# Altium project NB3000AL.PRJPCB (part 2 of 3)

## Sheet FPGA_Bypass_3V3.SCHDOC: FPGA Bypass 3V3
size A4; Organization: Altium Limited.; Address1: Level 3, 12a Rodborough Rd; Address2: Frenchs Forest 2086; Address3: NSW; Address4: AUSTRALIA; DocumentNumber: 58; SheetNumber: 59; SheetTotal: 78; PageSetup: Record=PageOptions|CenterHorizontal=True|CenterVertical=True|PrintScale=0.97|XCorrection=1.00|YCorrection=1.00|PrintKind=0|BorderSize=5000000|LeftOffset=0|BottomOffset=0|Orientation=2|PaperLength=1000|PaperWidth=1000|Scale=100|PaperSource=7|PrintQuality=-4|MediaType=1|DitherType=10|PaperKind=A4 (210 x 297 mm)|PrintScaleMode=1
Used 2 times, as channels USER_DECOUPLING_CAPS_3V3, HOST_DECOUPLING_CAPS_3V3. Parts and nets are listed once, with the designators drawn on the sheet.
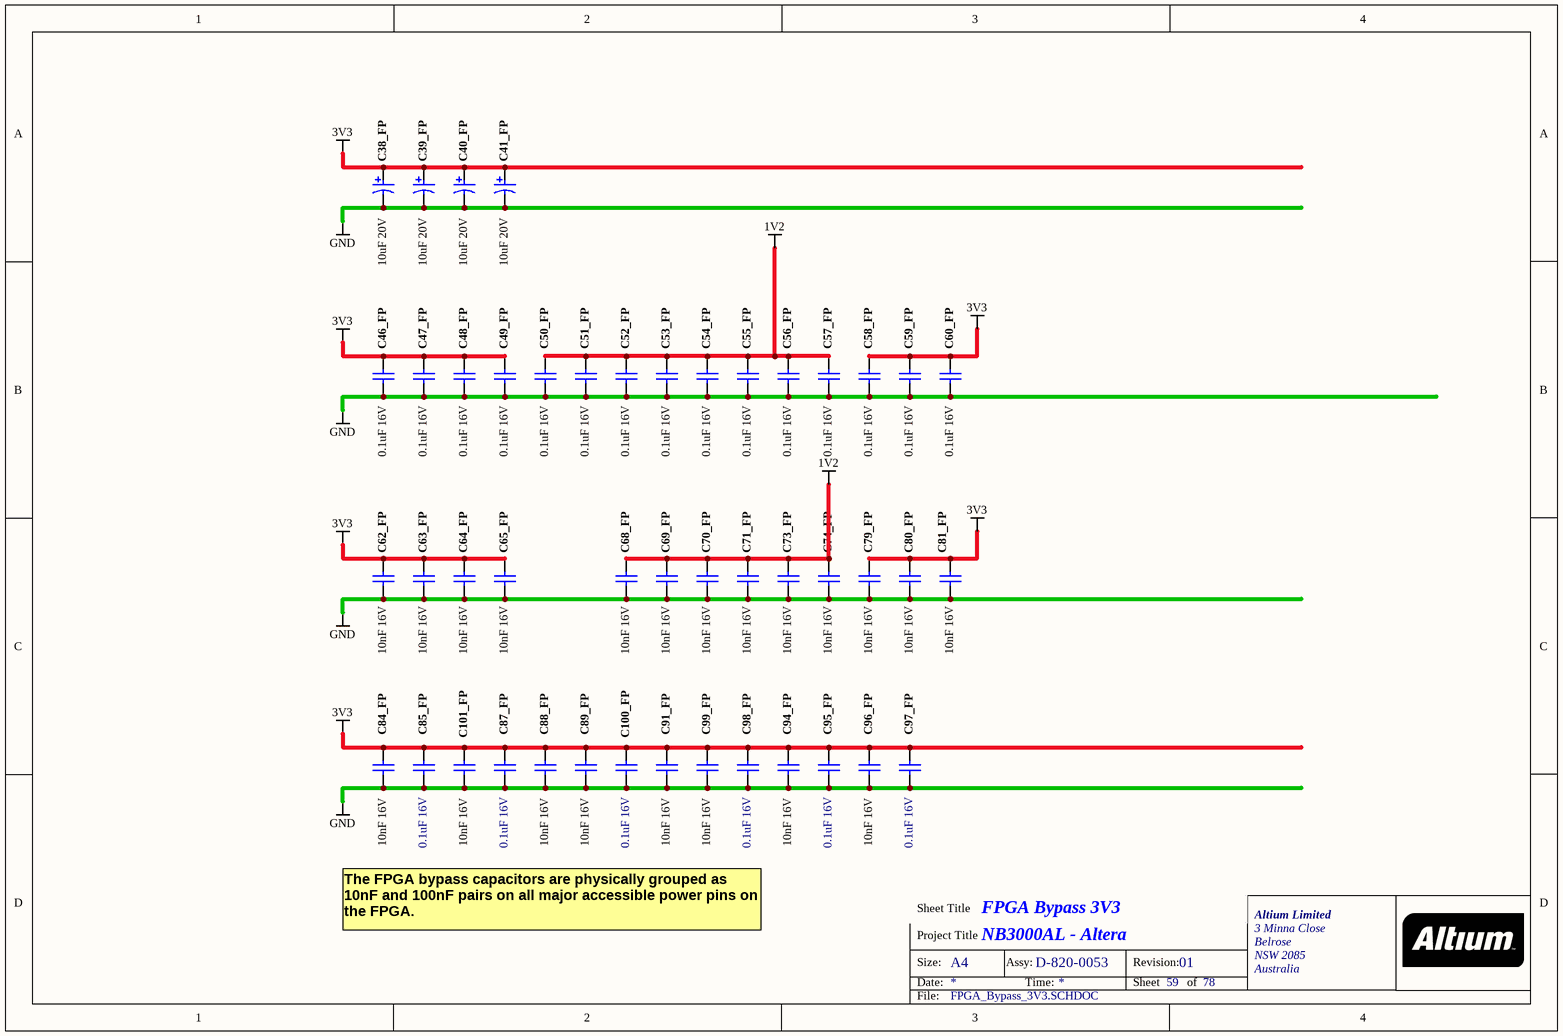
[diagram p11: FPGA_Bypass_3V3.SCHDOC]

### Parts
C38_FP  10uF 20V  [CAPC3528-STAR]
C39_FP  10uF 20V  [CAPC3528-STAR]
C40_FP  10uF 20V  [CAPC3528-STAR]
C41_FP  10uF 20V  [CAPC3528-STAR]
C46_FP  0.1uF 16V  [CAPC1005-STAR]
C47_FP  0.1uF 16V  [CAPC1005-STAR]
C48_FP  0.1uF 16V  [CAPC1005-STAR]
C49_FP  0.1uF 16V  [CAPC1005-STAR]
C50_FP  0.1uF 16V  [CAPC1005-STAR]
C51_FP  0.1uF 16V  [CAPC1005-STAR]
C52_FP  0.1uF 16V  [CAPC1005-STAR]
C53_FP  0.1uF 16V  [CAPC1005-STAR]
C54_FP  0.1uF 16V  [CAPC1005-STAR]
C55_FP  0.1uF 16V  [CAPC1005-STAR]
C56_FP  0.1uF 16V  [CAPC1005-STAR]
C57_FP  0.1uF 16V  [CAPC1005-STAR]
C58_FP  0.1uF 16V  [CAPC1005-STAR]
C59_FP  0.1uF 16V  [CAPC1005-STAR]
C60_FP  0.1uF 16V  [CAPC1005-STAR]
C62_FP  10nF 16V  [CAPC1005-STAR]
C63_FP  10nF 16V  [CAPC1005-STAR]
C64_FP  10nF 16V  [CAPC1005-STAR]
C65_FP  10nF 16V  [CAPC1005-STAR]
C68_FP  10nF 16V  [CAPC1005-STAR]
C69_FP  10nF 16V  [CAPC1005-STAR]
C70_FP  10nF 16V  [CAPC1005-STAR]
C71_FP  10nF 16V  [CAPC1005-STAR]
C73_FP  10nF 16V  [CAPC1005-STAR]
C74_FP  10nF 16V  [CAPC1005-STAR]
C79_FP  10nF 16V  [CAPC1005-STAR]
C80_FP  10nF 16V  [CAPC1005-STAR]
C81_FP  10nF 16V  [CAPC1005-STAR]
C84_FP  10nF 16V  [CAPC1005-STAR]
C85_FP  0.1uF 16V  [CAPC1005-STAR]
C87_FP  0.1uF 16V  [CAPC1005-STAR]
C88_FP  10nF 16V  [CAPC1005-STAR]
C89_FP  10nF 16V  [CAPC1005-STAR]
C91_FP  10nF 16V  [CAPC1005-STAR]
C94_FP  10nF 16V  [CAPC1005-STAR]
C95_FP  0.1uF 16V  [CAPC1005-STAR]
C96_FP  10nF 16V  [CAPC1005-STAR]
C97_FP  0.1uF 16V  [CAPC1005-STAR]
C98_FP  0.1uF 16V  [CAPC1005-STAR]
C99_FP  10nF 16V  [CAPC1005-STAR]
C100_FP  0.1uF 16V  [CAPC1005-STAR]
C101_FP  10nF 16V  [CAPC1005-STAR]

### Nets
1V2: C50_FP.1 C51_FP.1 C52_FP.1 C53_FP.1 C54_FP.1 C55_FP.1 C56_FP.1 C57_FP.1 C68_FP.1 C69_FP.1 C70_FP.1 C71_FP.1 C73_FP.1 C74_FP.1
3V3: C38_FP.1 C39_FP.1 C40_FP.1 C41_FP.1 C46_FP.1 C47_FP.1 C48_FP.1 C49_FP.1 C58_FP.1 C59_FP.1 C60_FP.1 C62_FP.1 C63_FP.1 C64_FP.1 C65_FP.1 C79_FP.1 C80_FP.1 C81_FP.1 C84_FP.1 C85_FP.1 C87_FP.1 C88_FP.1 C89_FP.1 C91_FP.1 C94_FP.1 C95_FP.1 C96_FP.1 C97_FP.1 C98_FP.1 C99_FP.1 C100_FP.1 C101_FP.1
GND: C38_FP.2 C39_FP.2 C40_FP.2 C41_FP.2 C46_FP.2 C47_FP.2 C48_FP.2 C49_FP.2 C50_FP.2 C51_FP.2 C52_FP.2 C53_FP.2 C54_FP.2 C55_FP.2 C56_FP.2 C57_FP.2 C58_FP.2 C59_FP.2 C60_FP.2 C62_FP.2 C63_FP.2 C64_FP.2 C65_FP.2 C68_FP.2 C69_FP.2 C70_FP.2 C71_FP.2 C73_FP.2 C74_FP.2 C79_FP.2 C80_FP.2 C81_FP.2 C84_FP.2 C85_FP.2 C87_FP.2 C88_FP.2 C89_FP.2 C91_FP.2 C94_FP.2 C95_FP.2 C96_FP.2 C97_FP.2 C98_FP.2 C99_FP.2 C100_FP.2 C101_FP.2

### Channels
USER_DECOUPLING_CAPS_3V3: designators end in A
HOST_DECOUPLING_CAPS_3V3: designators end in B

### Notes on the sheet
- The FPGA bypass capacitors are physically grouped as 10nF and 100nF pairs on all major accessible power pins on the FPGA.

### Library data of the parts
C38_FP C39_FP C40_FP C41_FP = D-101-0007: Capacitor, Tantalum, 10uF 10% 20V MCCT-B (3528); Polarity: Polarized
C46_FP C47_FP C48_FP C49_FP C50_FP C51_FP C52_FP C53_FP C54_FP C55_FP C56_FP C57_FP C58_FP C59_FP C60_FP C85_FP C87_FP C95_FP C97_FP C98_FP C100_FP = D-101-0080: Capacitor, Ceramic, 0.1uF 10% 16V 0402 (1005) X7R; Polarity: Non-Polarized
C62_FP C63_FP C64_FP C65_FP C68_FP C69_FP C70_FP C71_FP C73_FP C74_FP C79_FP C80_FP C81_FP C84_FP C88_FP C89_FP C91_FP C94_FP C96_FP C99_FP C101_FP = D-101-0077: Capacitor, Ceramic, 10nF 10% 16V 0402 (1005) X7R; Polarity: Non-Polarized

## Sheet FPGA_NonIO.SchDoc: User FPGA Pwr and Programming
size A3; Organization: Altium Limited.; Address1: Level 3, 12a Rodborough Rd; Address2: Frenchs Forest 2086; Address3: NSW; Address4: AUSTRALIA; DocumentNumber: 8; SheetNumber: 9; SheetTotal: 78
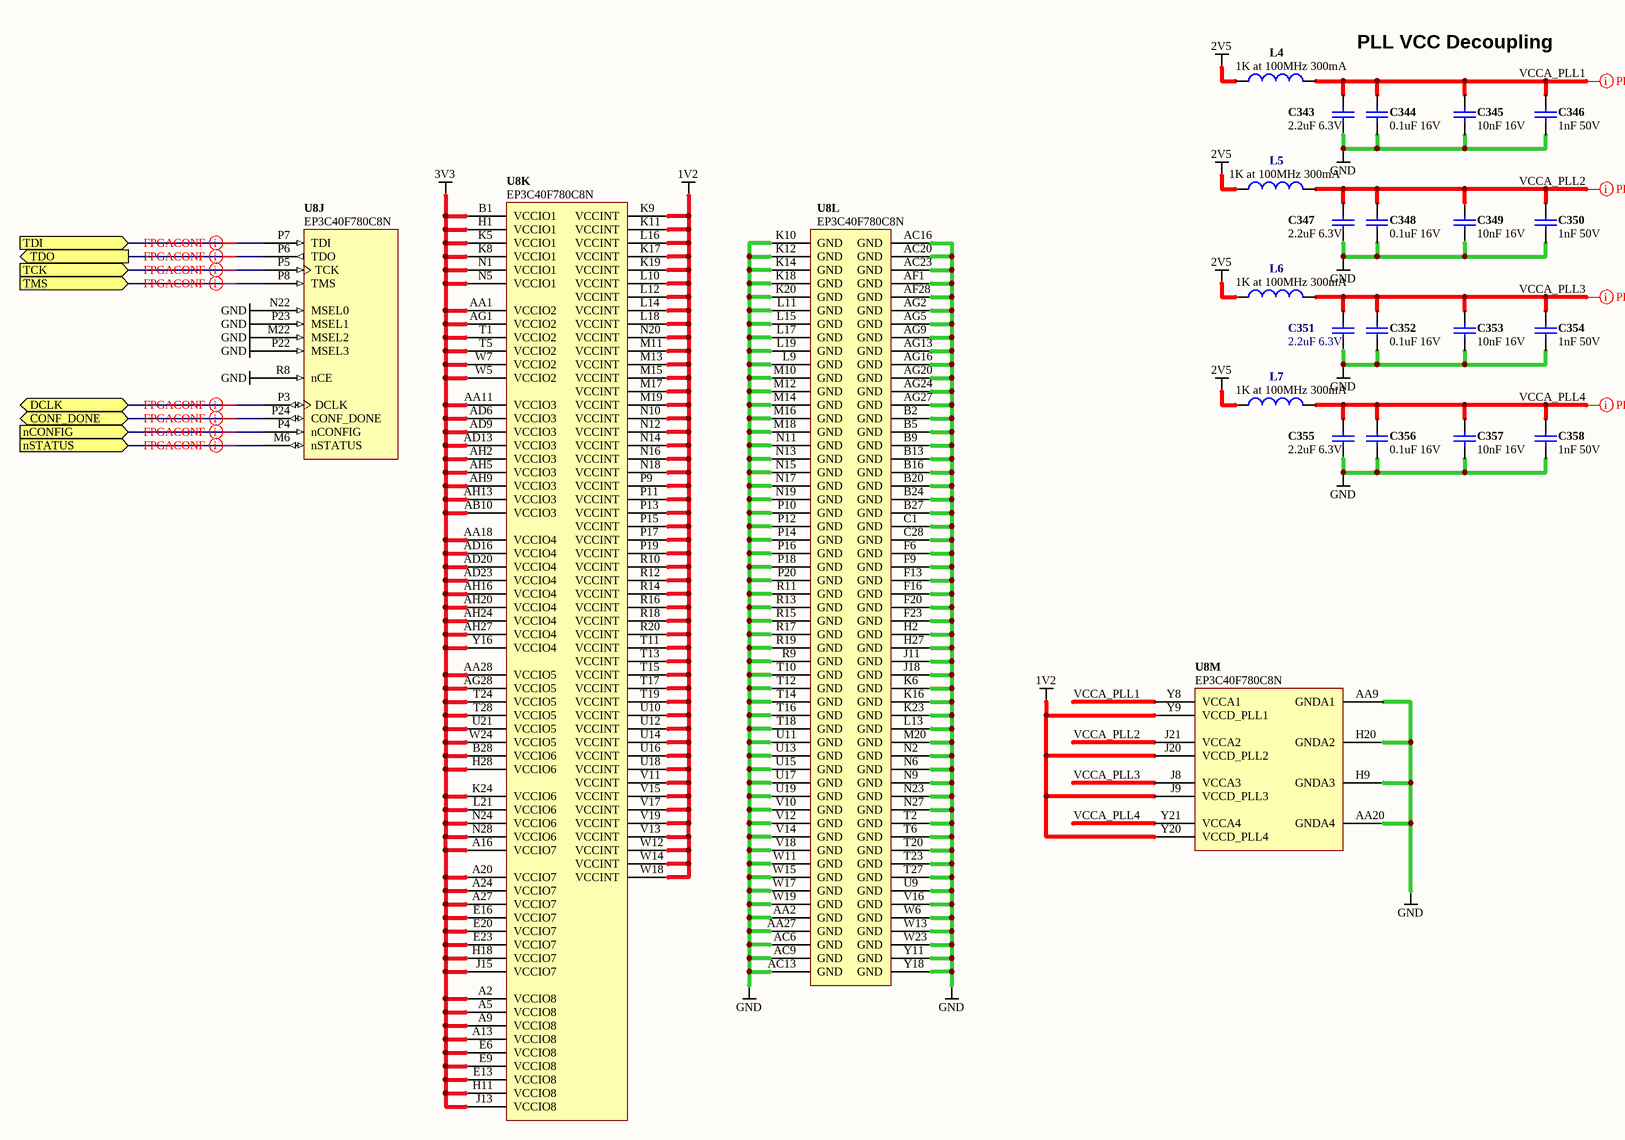
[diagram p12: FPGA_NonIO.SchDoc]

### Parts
C343  2.2uF 6.3V  [CAPC1005-STAR]
C344  0.1uF 16V  [CAPC1005-STAR]
C345  10nF 16V  [CAPC1005-STAR]
C346  1nF 50V  [CAPC1005-STAR]
C347  2.2uF 6.3V  [CAPC1005-STAR]
C348  0.1uF 16V  [CAPC1005-STAR]
C349  10nF 16V  [CAPC1005-STAR]
C350  1nF 50V  [CAPC1005-STAR]
C351  2.2uF 6.3V  [CAPC1005-STAR]
C352  0.1uF 16V  [CAPC1005-STAR]
C353  10nF 16V  [CAPC1005-STAR]
C354  1nF 50V  [CAPC1005-STAR]
C355  2.2uF 6.3V  [CAPC1005-STAR]
C356  0.1uF 16V  [CAPC1005-STAR]
C357  10nF 16V  [CAPC1005-STAR]
C358  1nF 50V  [CAPC1005-STAR]
L4  1K at 100MHz 300mA  [INDC1005]
L5  1K at 100MHz 300mA  [INDC1005]
L6  1K at 100MHz 300mA  [INDC1005]
L7  1K at 100MHz 300mA  [INDC1005]
U8  EP3C40F780C8N  [FBGA780-2]  (parts J,K,L,M of 13)

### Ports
CONF_DONE (bidir), DCLK (bidir), nCONFIG (in), nSTATUS (in), TCK (in), TDI (in), TDO (out), TMS (in)

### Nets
1V2: U8.J9(VCCD_PLL3) U8.J20(VCCD_PLL2) U8.K9(VCCINT) U8.K11(VCCINT) U8.K17(VCCINT) U8.K19(VCCINT) U8.L10(VCCINT) U8.L12(VCCINT) U8.L14(VCCINT) U8.L16(VCCINT) U8.L18(VCCINT) U8.M11(VCCINT) U8.M13(VCCINT) U8.M15(VCCINT) U8.M17(VCCINT) U8.M19(VCCINT) U8.N10(VCCINT) U8.N12(VCCINT) U8.N14(VCCINT) U8.N16(VCCINT) U8.N18(VCCINT) U8.N20(VCCINT) U8.P9(VCCINT) U8.P11(VCCINT) U8.P13(VCCINT) U8.P15(VCCINT) U8.P17(VCCINT) U8.P19(VCCINT) U8.R10(VCCINT) U8.R12(VCCINT) U8.R14(VCCINT) U8.R16(VCCINT) U8.R18(VCCINT) U8.R20(VCCINT) U8.T11(VCCINT) U8.T13(VCCINT) U8.T15(VCCINT) U8.T17(VCCINT) U8.T19(VCCINT) U8.U10(VCCINT) U8.U12(VCCINT) U8.U14(VCCINT) U8.U16(VCCINT) U8.U18(VCCINT) U8.V11(VCCINT) U8.V13(VCCINT) U8.V15(VCCINT) U8.V17(VCCINT) U8.V19(VCCINT) U8.W12(VCCINT) U8.W14(VCCINT) U8.W18(VCCINT) U8.Y9(VCCD_PLL1) U8.Y20(VCCD_PLL4)
2V5: L4.1 L5.1 L6.1 L7.1
3V3: U8.A2(VCCIO8) U8.A5(VCCIO8) U8.A9(VCCIO8) U8.A13(VCCIO8) U8.A16(VCCIO7) U8.A20(VCCIO7) U8.A24(VCCIO7) U8.A27(VCCIO7) U8.AA1(VCCIO2) U8.AA11(VCCIO3) U8.AA18(VCCIO4) U8.AA28(VCCIO5) U8.AB10(VCCIO3) U8.AD6(VCCIO3) U8.AD9(VCCIO3) U8.AD13(VCCIO3) U8.AD16(VCCIO4) U8.AD20(VCCIO4) U8.AD23(VCCIO4) U8.AG1(VCCIO2) U8.AG28(VCCIO5) U8.AH2(VCCIO3) U8.AH5(VCCIO3) U8.AH9(VCCIO3) U8.AH13(VCCIO3) U8.AH16(VCCIO4) U8.AH20(VCCIO4) U8.AH24(VCCIO4) U8.AH27(VCCIO4) U8.B1(VCCIO1) U8.B28(VCCIO6) U8.E6(VCCIO8) U8.E9(VCCIO8) U8.E13(VCCIO8) U8.E16(VCCIO7) U8.E20(VCCIO7) U8.E23(VCCIO7) U8.H1(VCCIO1) U8.H11(VCCIO8) U8.H18(VCCIO7) U8.H28(VCCIO6) U8.J13(VCCIO8) U8.J15(VCCIO7) U8.K5(VCCIO1) U8.K8(VCCIO1) U8.K24(VCCIO6) U8.L21(VCCIO6) U8.N1(VCCIO1) U8.N5(VCCIO1) U8.N24(VCCIO6) U8.N28(VCCIO6) U8.T1(VCCIO2) U8.T5(VCCIO2) U8.T24(VCCIO5) U8.T28(VCCIO5) U8.U21(VCCIO5) U8.W5(VCCIO2) U8.W7(VCCIO2) U8.W24(VCCIO5) U8.Y16(VCCIO4)
GND: C343.2 C344.2 C345.2 C346.2 C347.2 C348.2 C349.2 C350.2 C351.2 C352.2 C353.2 C354.2 C355.2 C356.2 C357.2 C358.2 U8.AA2(GND) U8.AA9(GNDA1) U8.AA20(GNDA4) U8.AA27(GND) U8.AC6(GND) U8.AC9(GND) U8.AC13(GND) U8.AC16(GND) U8.AC20(GND) U8.AC23(GND) U8.AF1(GND) U8.AF28(GND) U8.AG2(GND) U8.AG5(GND) U8.AG9(GND) U8.AG13(GND) U8.AG16(GND) U8.AG20(GND) U8.AG24(GND) U8.AG27(GND) U8.B2(GND) U8.B5(GND) U8.B9(GND) U8.B13(GND) U8.B16(GND) U8.B20(GND) U8.B24(GND) U8.B27(GND) U8.C1(GND) U8.C28(GND) U8.F6(GND) U8.F9(GND) U8.F13(GND) U8.F16(GND) U8.F20(GND) U8.F23(GND) U8.H2(GND) U8.H9(GNDA3) U8.H20(GNDA2) U8.H27(GND) U8.J11(GND) U8.J18(GND) U8.K6(GND) U8.K10(GND) U8.K12(GND) U8.K14(GND) U8.K16(GND) U8.K18(GND) U8.K20(GND) U8.K23(GND) U8.L9(GND) U8.L11(GND) U8.L13(GND) U8.L15(GND) U8.L17(GND) U8.L19(GND) U8.M10(GND) U8.M12(GND) U8.M14(GND) U8.M16(GND) U8.M18(GND) U8.M20(GND) U8.M22(MSEL2) U8.N2(GND) U8.N6(GND) U8.N9(GND) U8.N11(GND) U8.N13(GND) U8.N15(GND) U8.N17(GND) U8.N19(GND) U8.N22(MSEL0) U8.N23(GND) U8.N27(GND) U8.P10(GND) U8.P12(GND) U8.P14(GND) U8.P16(GND) U8.P18(GND) U8.P20(GND) U8.P22(MSEL3) U8.P23(MSEL1) U8.R8(nCE) U8.R9(GND) U8.R11(GND) U8.R13(GND) U8.R15(GND) U8.R17(GND) U8.R19(GND) U8.T2(GND) U8.T6(GND) U8.T10(GND) U8.T12(GND) U8.T14(GND) U8.T16(GND) U8.T18(GND) U8.T20(GND) U8.T23(GND) U8.T27(GND) U8.U9(GND) U8.U11(GND) U8.U13(GND) U8.U15(GND) U8.U17(GND) U8.U19(GND) U8.V10(GND) U8.V12(GND) U8.V14(GND) U8.V16(GND) U8.V18(GND) U8.W6(GND) U8.W11(GND) U8.W13(GND) U8.W15(GND) U8.W17(GND) U8.W19(GND) U8.W23(GND) U8.Y11(GND) U8.Y18(GND)
CONF_DONE: U8.P24(CONF_DONE) ; port CONF_DONE
DCLK: U8.P3(DCLK) ; port DCLK
nCONFIG: U8.P4(nCONFIG) ; port nCONFIG
nSTATUS: U8.M6(nSTATUS) ; port nSTATUS
TCK: U8.P5(TCK) ; port TCK
TDI: U8.P7(TDI) ; port TDI
TDO: U8.P6(TDO) ; port TDO
TMS: U8.P8(TMS) ; port TMS
VCCA_PLL1: C343.1 C344.1 C345.1 C346.1 L4.2 U8.Y8(VCCA1)
VCCA_PLL2: C347.1 C348.1 C349.1 C350.1 L5.2 U8.J21(VCCA2)
VCCA_PLL3: C351.1 C352.1 C353.1 C354.1 L6.2 U8.J8(VCCA3)
VCCA_PLL4: C355.1 C356.1 C357.1 C358.1 L7.2 U8.Y21(VCCA4)

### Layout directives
net class FPGACONF: CONF_DONE, DCLK, nCONFIG, nSTATUS, TCK, TDI, TDO, TMS
net class PLL: VCCA_PLL1, VCCA_PLL2, VCCA_PLL3, VCCA_PLL4

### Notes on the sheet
- PLL VCC Decoupling

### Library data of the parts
C343 C347 C351 C355 = D-101-0112: Capacitor, Ceramic, 2.2uF 10% 6.3V 0402 (1005) X5R; Polarity: Non-Polarized; Tolerance: 20 %
C344 C348 C352 C356 = D-101-0080: as C46_FP on sheet FPGA_Bypass_3V3
C345 C349 C353 C357 = D-101-0077: as C62_FP on sheet FPGA_Bypass_3V3
C346 C350 C354 C358 = D-101-0030: Capacitor, Ceramic, 1nF 10% 50V 0402 (1005) X7R; Polarity: Non-Polarized
L4-L7 = D-102-0026: Inductor, Ferrite Bead 1K@100MHz 300mA 0402 BK1005HS102-T; Inductance: nH
U8 = D-241-0023: FPGA, Altera Cyclone3-40 F780; Supply Voltage: mV

## Sheet PULLDNx3.SCHDOC: Visual Indicators Top
size A4; DocumentNumber: 10; SheetNumber: 11; SheetTotal: 78
Used 10 times, as channels PULLDOWN, PULLDOWN, PULLDOWN, PULLDOWN, PULLDOWN, PULLDOWN, PULLDOWN, PULLDOWN, PULLDOWN, PULLDOWN. Parts and nets are listed once, with the designators drawn on the sheet.
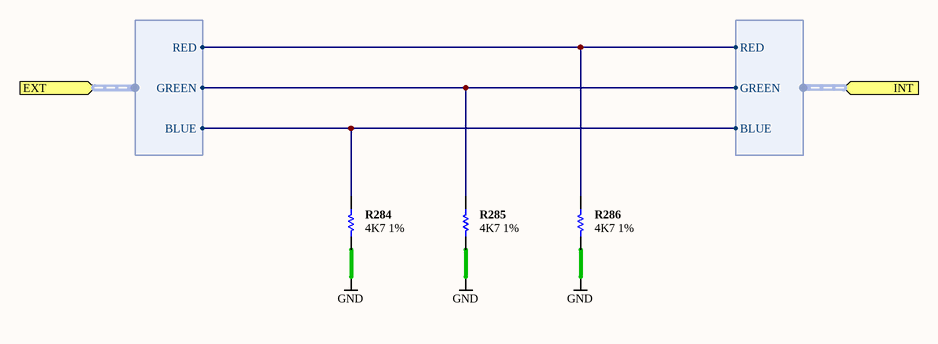
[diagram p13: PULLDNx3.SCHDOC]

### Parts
R284  4K7 1%  [RESC1005-STAR]
R285  4K7 1%  [RESC1005-STAR]
R286  4K7 1%  [RESC1005-STAR]

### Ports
EXT (harness RGB_LED), INT (harness RGB_LED)

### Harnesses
RGB_LED: GREEN, RED, BLUE

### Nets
GND: R284.1 R285.1 R286.1
NetR284_2: R284.2 ; port EXT.BLUE, port INT.BLUE
NetR285_2: R285.2 ; port EXT.GREEN, port INT.GREEN
NetR286_2: R286.2 ; port EXT.RED, port INT.RED

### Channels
PULLDOWN: designators end in A
PULLDOWN: designators end in B
PULLDOWN: designators end in C
PULLDOWN: designators end in D
PULLDOWN: designators end in E
PULLDOWN: designators end in F
PULLDOWN: designators end in G
PULLDOWN: designators end in H
PULLDOWN: designators end in I
PULLDOWN: designators end in J

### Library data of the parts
R284-R286 = D-100-0088: Resistor, 4K7 1% 0402 (1005); Power Rating: 63 mW; Resistance: 4.7 K

## Sheet LED_RGB_SMDx8.SCHDOC: Visual Indicators Top
size A4; DocumentNumber: 10; SheetNumber: 11; SheetTotal: 78
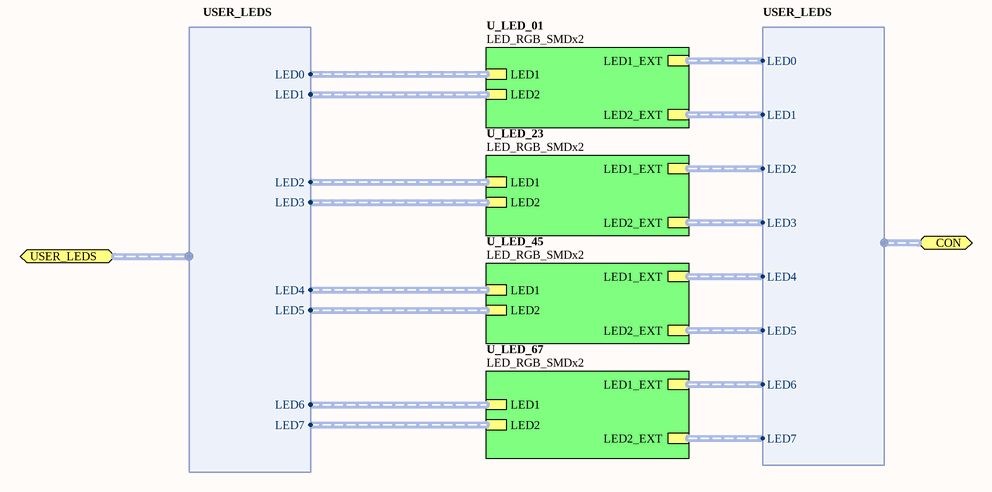
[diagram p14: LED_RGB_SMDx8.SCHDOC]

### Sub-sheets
U_LED_01 = LED_RGB_SMDx2 (file not in this document): LED1 (harness RGB_LED), LED2 (harness RGB_LED), LED1_EXT (harness RGB_LED), LED2_EXT (harness RGB_LED)
U_LED_23 = LED_RGB_SMDx2 (file not in this document): LED1 (harness RGB_LED), LED2 (harness RGB_LED), LED1_EXT (harness RGB_LED), LED2_EXT (harness RGB_LED)
U_LED_45 = LED_RGB_SMDx2 (file not in this document): LED1 (harness RGB_LED), LED2 (harness RGB_LED), LED1_EXT (harness RGB_LED), LED2_EXT (harness RGB_LED)
U_LED_67 = LED_RGB_SMDx2 (file not in this document): LED1 (harness RGB_LED), LED2 (harness RGB_LED), LED1_EXT (harness RGB_LED), LED2_EXT (harness RGB_LED)

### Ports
CON (harness USER_LEDS), USER_LEDS (harness USER_LEDS)

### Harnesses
USER_LEDS: LED0, LED1, LED2, LED3, LED4, LED5, LED6, LED7

## Sheet PWJACK+SWITCH.SchDoc: Power Jack & Switch
size A4; Organization: Altium Limited.; Address1: Level 3, 12a Rodborough Rd; Address2: Frenchs Forest 2086; Address3: NSW; Address4: AUSTRALIA; DocumentNumber: 20; Revision: 6; SheetNumber: 21; SheetTotal: 78
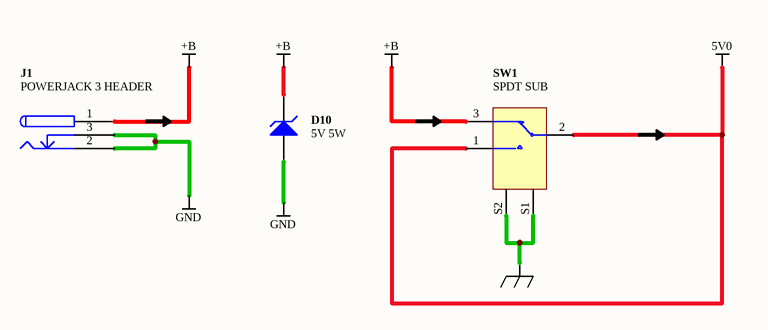
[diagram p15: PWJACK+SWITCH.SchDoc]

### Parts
(Parts that share a designator on the sheet are numbered #1, #2 ... from top to bottom, then left to right.)
D10  5V 5W  [DIOM8059]
J1#2  POWERJACK 3 HEADER  [KLD-0202]
SW1  SPDT SUB  [T8019L-TNQ]

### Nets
5V0: SW1.1 SW1.2
+B: D10.2(K) J1#2.1 SW1.3
GND: D10.1(A) J1#2.2 J1#2.3
SHIELD: SW1.S1 SW1.S2

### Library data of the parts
D10 = D-150-0001: Zener Diode, 5V 5W; Max Forward Current: mA; Rated Voltage: mV
J1#2 = D-300-0007: Connector, 3 Conductor Power Jack 2 break 2 aux contacts
SW1 = D-301-0000: Switch, SPDT Subminiature Toggle

## Sheet Ethernet_RTL8201CL.SchDoc: Ethernet Interface
size A3; DocumentNumber: 21; SheetNumber: 22; SheetTotal: 78; Organization: Altium Limited.; Address1: Level 3, 12a Rodborough Rd; Address2: Frenchs Forest 2086; Address3: NSW; Address4: AUSTRALIA
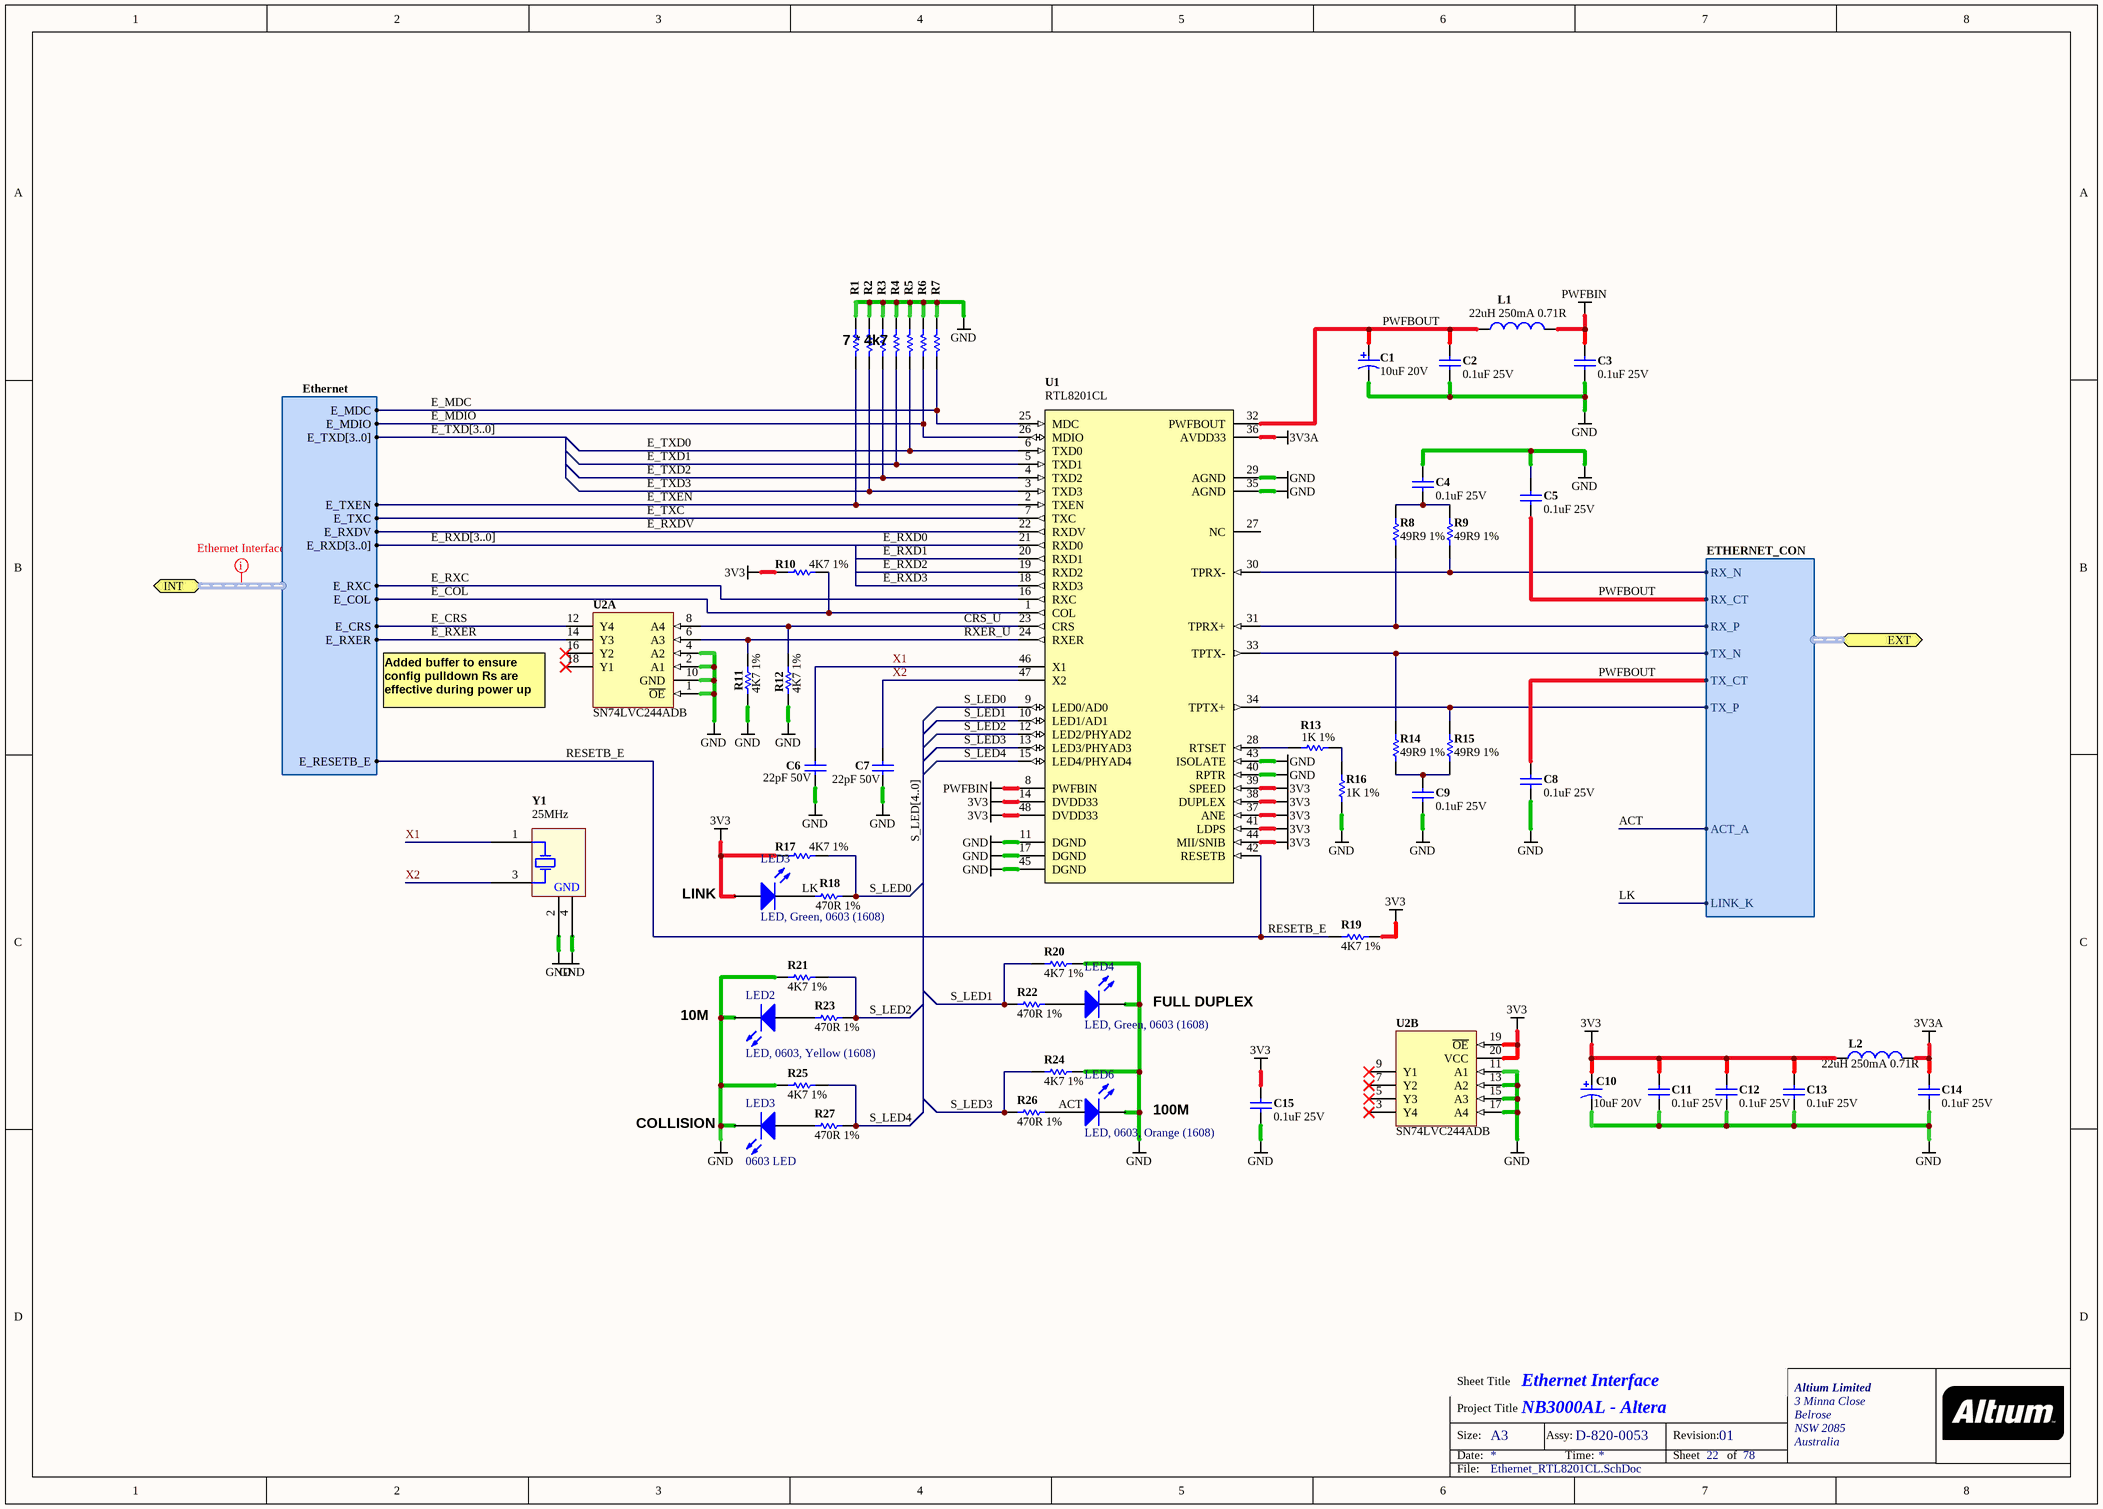
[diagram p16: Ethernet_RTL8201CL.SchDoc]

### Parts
(Parts that share a designator on the sheet are numbered #1, #2 ... from top to bottom, then left to right.)
C1#3  10uF 20V  [CAPC3528-STAR]
C2#3  0.1uF 25V  [CAPC1005-STAR]
C3#3  0.1uF 25V  [CAPC1005-STAR]
C4#3  0.1uF 25V  [CAPC1005-STAR]
C5#2  0.1uF 25V  [CAPC1005-STAR]
C6#1  22pF 50V  [CAPC1005-STAR]
C7#1  22pF 50V  [CAPC1005-STAR]
C8#1  0.1uF 25V  [CAPC1005-STAR]
C9#1  0.1uF 25V  [CAPC1005-STAR]
C10  10uF 20V  [CAPC3528-STAR]
C11  0.1uF 25V  [CAPC1005-STAR]
C12  0.1uF 25V  [CAPC1005-STAR]
C13  0.1uF 25V  [CAPC1005-STAR]
C14  0.1uF 25V  [CAPC1005-STAR]
C15  0.1uF 25V  [CAPC1005-STAR]
L1#2  22uH 250mA 0.71R  [INDC3225]
L2  22uH 250mA 0.71R  [INDC3225]
LED2  LED, 0603, Yellow (1608)  [0603LED_YELLOW]
LED3#1  LED, Green, 0603 (1608)  [0603LED_GREEN]
LED3#2  0603 LED  [0603LED_RED]
LED4  LED, Green, 0603 (1608)  [0603LED_GREEN]
LED6  LED, 0603, Orange (1608)  [0603LED_ORANGE]
R1#3  4K7 1%  [RESC1005-STAR]  (value not drawn)
R2#3  4K7 1%  [RESC1005-STAR]  (value not drawn)
R3#3  4K7 1%  [RESC1005-STAR]  (value not drawn)
R4#3  4K7 1%  [RESC1005-STAR]  (value not drawn)
R5#2  4K7 1%  [RESC1005-STAR]  (value not drawn)
R6#2  4K7 1%  [RESC1005-STAR]  (value not drawn)
R7#2  4K7 1%  [RESC1005-STAR]  (value not drawn)
R8#2  49R9 1%  [RESC2012-STAR]
R9#2  49R9 1%  [RESC2012-STAR]
R10#2  4K7 1%  [RESC1005-STAR]
R11  4K7 1%  [RESC1005-STAR]
R12#2  4K7 1%  [RESC1005-STAR]
R13  1K 1%  [RESC1005-STAR]
R14#2  49R9 1%  [RESC2012-STAR]
R15  49R9 1%  [RESC2012-STAR]
R16  1K 1%  [RESC1005-STAR]
R17  4K7 1%  [RESC1005-STAR]
R18#2  470R 1%  [RESC1005-STAR]
R19  4K7 1%  [RESC1005-STAR]
R20#2  4K7 1%  [RESC1005-STAR]
R21  4K7 1%  [RESC1005-STAR]
R22#2  470R 1%  [RESC1005-STAR]
R23#2  470R 1%  [RESC1005-STAR]
R24#2  4K7 1%  [RESC1005-STAR]
R25  4K7 1%  [RESC1005-STAR]
R26  470R 1%  [RESC1005-STAR]
R27  470R 1%  [RESC1005-STAR]
U1#3  RTL8201CL  [TSQFP50P900X900-48]
U2#1  SN74LVC244ADB  [SOP65P780-20]  (parts A,B of 2)
Y1#1  25MHz  [XTAL-200X126-4]

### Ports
EXT (harness ETHERNET_CON), INT (harness Ethernet)

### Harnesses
Ethernet: E_MDC, E_MDIO, E_TXD[3..0], E_TXC, E_TXEN, E_RXDV, E_RXD[3..0], E_RESETB_E, E_RXC, E_COL, E_CRS, E_RXER
ETHERNET_CON: TX_P, TX_N, RX_P, RX_N, RX_CT, TX_CT, LINK_K, ACT_A

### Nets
3V3: C10.1 C11.2 C12.2 C13.2 C15.2 L2.1 LED3#1.1(A) R10#2.2 R17.2 R19.2 U1#3.14(DVDD33) U1#3.37(ANE) U1#3.38(DUPLEX) U1#3.39(SPEED) U1#3.41(LDPS) U1#3.44(MII/SNIB) U1#3.48(DVDD33) U2#1.19(~{OE}) U2#1.20(VCC)
3V3A: C14.2 L2.2 U1#3.36(AVDD33)
GND: C1#3.2 C2#3.1 C3#3.1 C4#3.2 C5#2.2 C6#1.1 C7#1.1 C8#1.1 C9#1.1 C10.2 C11.1 C12.1 C13.1 C14.1 C15.1 LED2.2(K) LED3#2.2(K) LED4.2(K) LED6.2(K) R1#3.2 R2#3.2 R3#3.2 R4#3.2 R5#2.2 R6#2.2 R7#2.2 R11.2 R12#2.2 R16.1 R20#2.1 R21.2 R24#2.1 R25.2 U1#3.11(DGND) U1#3.17(DGND) U1#3.29(AGND) U1#3.35(AGND) U1#3.40(RPTR) U1#3.43(ISOLATE) U1#3.45(DGND) U2#1.1(~{OE}) U2#1.2(A1) U2#1.4(A2) U2#1.10(GND) U2#1.11(A1) U2#1.13(A2) U2#1.15(A3) U2#1.17(A4) Y1#1.2(GND) Y1#1.4(GND)
PWFBIN: C3#3.2 L1#2.2 U1#3.8(PWFBIN)
ACT: LED6.1(A) R26.2 ; port EXT.ACT_A
CRS_U: R12#2.1 U1#3.23(CRS) U2#1.8(A4)
E_COL: R10#2.1 U1#3.1(COL) ; port INT.E_COL
E_CRS: U2#1.12(Y4) ; port INT.E_CRS
E_MDC: R7#2.1 U1#3.25(MDC) ; port INT.E_MDC
E_MDIO: R6#2.1 U1#3.26(MDIO) ; port INT.E_MDIO
E_RXC: U1#3.16(RXC) ; port INT.E_RXC
E_RXD0: U1#3.21(RXD0)
E_RXD1: U1#3.20(RXD1)
E_RXD2: U1#3.19(RXD2)
E_RXD3: U1#3.18(RXD3)
E_RXDV: U1#3.22(RXDV) ; port INT.E_RXDV
E_RXER: U2#1.14(Y3) ; port INT.E_RXER
E_TXC: U1#3.7(TXC) ; port INT.E_TXC
E_TXD0: R5#2.1 U1#3.6(TXD0)
E_TXD1: R4#3.1 U1#3.5(TXD1)
E_TXD2: R3#3.1 U1#3.4(TXD2)
E_TXD3: R2#3.1 U1#3.3(TXD3)
E_TXEN: R1#3.1 U1#3.2(TXEN) ; port INT.E_TXEN
LK: LED3#1.2(K) R18#2.2 ; port EXT.LINK_K
PWFBOUT: C1#3.1 C2#3.2 C5#2.1 C8#1.2 L1#2.1 U1#3.32(PWFBOUT) ; port EXT.RX_CT, port EXT.TX_CT
RESETB_E: R19.1 U1#3.42(RESETB) ; port INT.E_RESETB_E
RXER_U: R11.1 U1#3.24(RXER) U2#1.6(A3)
S_LED0: R17.1 R18#2.1 U1#3.9(LED0/AD0)
S_LED1: R20#2.2 R22#2.1 U1#3.10(LED1/AD1)
S_LED2: R21.1 R23#2.1 U1#3.12(LED2/PHYAD2)
S_LED3: R24#2.2 R26.1 U1#3.13(LED3/PHYAD3)
S_LED4: R25.1 R27.1 U1#3.15(LED4/PHYAD4)
X1: C6#1.2 U1#3.46(X1) Y1#1.1(X1)
X2: C7#1.2 U1#3.47(X2) Y1#1.3(X2)
NetC4#3_1: C4#3.1 R8#2.2 R9#2.2
NetC9#1_2: C9#1.2 R14#2.1 R15.1
NetLED2_1: LED2.1(A) R23#2.2
NetLED3#2_1: LED3#2.1(A) R27.2
NetLED4_1: LED4.1(A) R22#2.2
NetR8#2_1: R8#2.1 U1#3.31(TPRX+) ; port EXT.RX_P
NetR9#2_1: R9#2.1 U1#3.30(TPRX-) ; port EXT.RX_N
NetR13_1: R13.1 R16.2
NetR13_2: R13.2 U1#3.28(RTSET)
NetR14#2_2: R14#2.2 U1#3.33(TPTX-) ; port EXT.TX_N
NetR15_2: R15.2 U1#3.34(TPTX+) ; port EXT.TX_P

Not connected (* = marked no-connect by the designer): U1#3 27(NC); U2#1 3(Y4)* 5(Y3)* 7(Y2)* 9(Y1)* 16(Y2)* 18(Y1)*

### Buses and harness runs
bus E_RXD[3..0]
bus E_TXD[3..0]
bus S_LED[4..0]

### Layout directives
net class Ethernet Interface: (no net found under the mark)

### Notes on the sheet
- (near R1#3) 7 * 4k7
- (near U2#1) Added buffer to ensure config pulldown Rs are effective during power up
- (near U2#1) LINK
- (near U2#1) 10M
- (near U2#1) FULL DUPLEX
- (near U2#1) COLLISION
- (near U2#1) 100M

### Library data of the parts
C1#3 C10 = D-101-0007: as C38_FP on sheet FPGA_Bypass_3V3
C2#3 C3#3 C4#3 C5#2 C8#1 C9#1 C11-C15 = D-101-0045: Capacitor, Ceramic, 0.1uF 25V 0402 (1005); Dielectric: X7R; Polarity: Non-Polarized; Tolerance: 10 %
C6#1 C7#1 = D-101-0059: Capacitor, Ceramic, 22pF 5% 50V 0402 (1005) COG; Polarity: Non-Polarized
L1#2 L2 = D-102-0006: Inductor, Coil 22uH  1210 (3225) LQH32CN220K21L; Max Input Current: mA
LED2 = D-153-0007: Brightness: 120mcd; Color: Yellow/Amber; Peak Wave Length: nm
LED3#1 LED4 = D-153-0002: Brightness: 50mcd; Peak Wave Length: nm
LED3#2 = D-153-0009: LED, Red 0603 (1608) 63mCd; Peak Wave Length: 630nm
LED6 = D-153-0006: Brightness: 200mcd; Peak Wave Length: nm
R1#3 R2#3 R3#3 R4#3 R5#2 R6#2 R7#2 R10#2 R11 R12#2 R17 R19 R20#2 R21 R24#2 R25 = D-100-0088: as R284-R286 on sheet PULLDNx3
R8#2 R9#2 R14#2 R15 = D-100-0017: Resistor, 49R9 1% 0805 (2012); Power Rating: mW; Resistance: 49.9 R
R13 R16 = D-100-0121: Resistor, 1K 1% 0402 (1005); Power Rating: 63 mW
R18#2 R22#2 R23#2 R26 R27 = D-100-0093: Resistor, 470R 1% 0402 (1005); Power Rating: 63 mW
U1#3 = D-221-0000: RTL8201CL-VD, Single-Chip/Single-Port 10/100 Fast Ethernet Phyceiver; Comm Standard: None
U2#1 = D-205-0000: SN74LVC244ADBR,  Octal Buffer/Driver with 3-State Outputs, 2.0V - 3.6V
Y1#1 = D-103-0030: Crystal, SMD, 25.000000MHz Stab=50ppm 18.0pF; Frequency Stability: 50ppm; Load Capacitance: 18pF; Nominal Operational Voltage: mV

## Sheet HOST_JTAG.SchDoc: Local MCU Debug Connector
size A4; DocumentNumber: 24; SheetNumber: 25; SheetTotal: 78
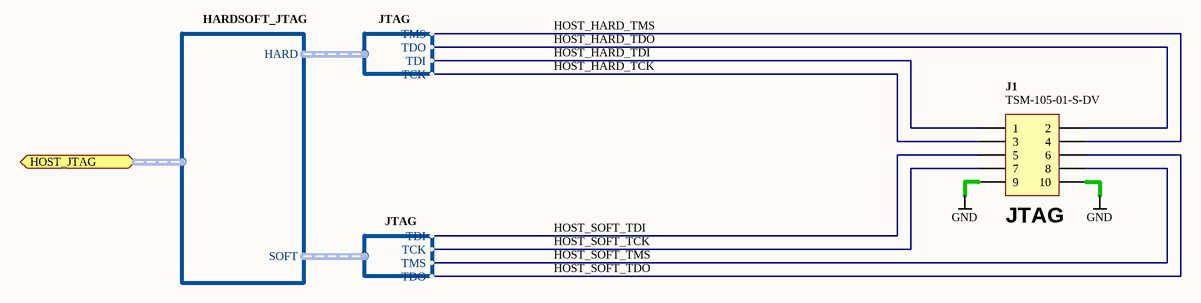
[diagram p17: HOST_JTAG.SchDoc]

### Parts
(Parts that share a designator on the sheet are numbered #1, #2 ... from top to bottom, then left to right.)
J1#3  TSM-105-01-S-DV  [TSM-105-01-DV]

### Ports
HOST_JTAG (harness HARDSOFT_JTAG)

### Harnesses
JTAG: TMS, TDO, TDI, TCK
HARDSOFT_JTAG: HARD, SOFT

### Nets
GND: J1#3.9 J1#3.10
HOST_HARD_TCK: J1#3.3 ; harness JTAG.TCK
HOST_HARD_TDI: J1#3.1 ; harness JTAG.TDI
HOST_HARD_TDO: J1#3.2 ; harness JTAG.TDO
HOST_HARD_TMS: J1#3.4 ; harness JTAG.TMS
HOST_SOFT_TCK: J1#3.7 ; harness JTAG.TCK
HOST_SOFT_TDI: J1#3.5 ; harness JTAG.TDI
HOST_SOFT_TDO: J1#3.6 ; harness JTAG.TDO
HOST_SOFT_TMS: J1#3.8 ; harness JTAG.TMS

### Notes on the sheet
- (near J1#3) JTAG

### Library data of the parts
J1#3 = D-300-0076: Non-Boxed Header IDC, 2 X 5 Pin SMD; Connector type: Boxed; Max Current: mA

## Sheet USERPWR.SchDoc: USER IO Power Loopback
size A4; Organization: Altium Limited.
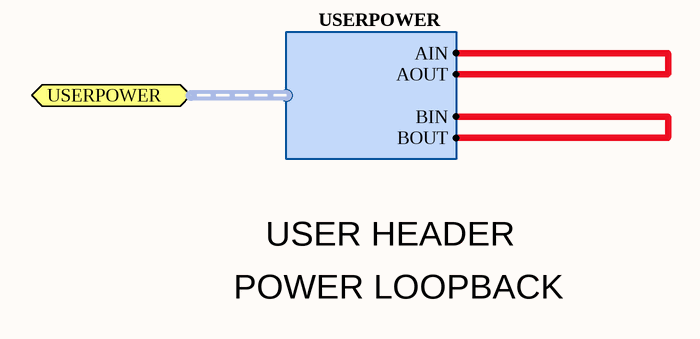
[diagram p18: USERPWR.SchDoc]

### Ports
USERPOWER (harness USERPOWER)

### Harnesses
USERPOWER: AIN, BIN, AOUT, BOUT

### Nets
(unnamed): port USERPOWER.AIN, port USERPOWER.AOUT
(unnamed): port USERPOWER.BIN, port USERPOWER.BOUT  [a separate net that carries the same name]

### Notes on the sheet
- POWER LOOPBACK
- USER HEADER

## Sheet Host_FPGA.SchDoc: Host Controller - Altera - EP3C10
size A2; Organization: Altium Limited.; Revision: 6; PageSetup: Record=PageOptions|CenterHorizontal=True|CenterVertical=True|PrintScale=0.47|XCorrection=1.00|YCorrection=1.00|PrintKind=0|BorderSize=5000000|LeftOffset=0|BottomOffset=0|Orientation=2|PaperLength=1000|PaperWidth=1000|Scale=100|PaperSource=7|PrintQuality=1200|MediaType=1|DitherType=10|PaperKind=A4 (210 x 297 mm)|PrintScaleMode=1
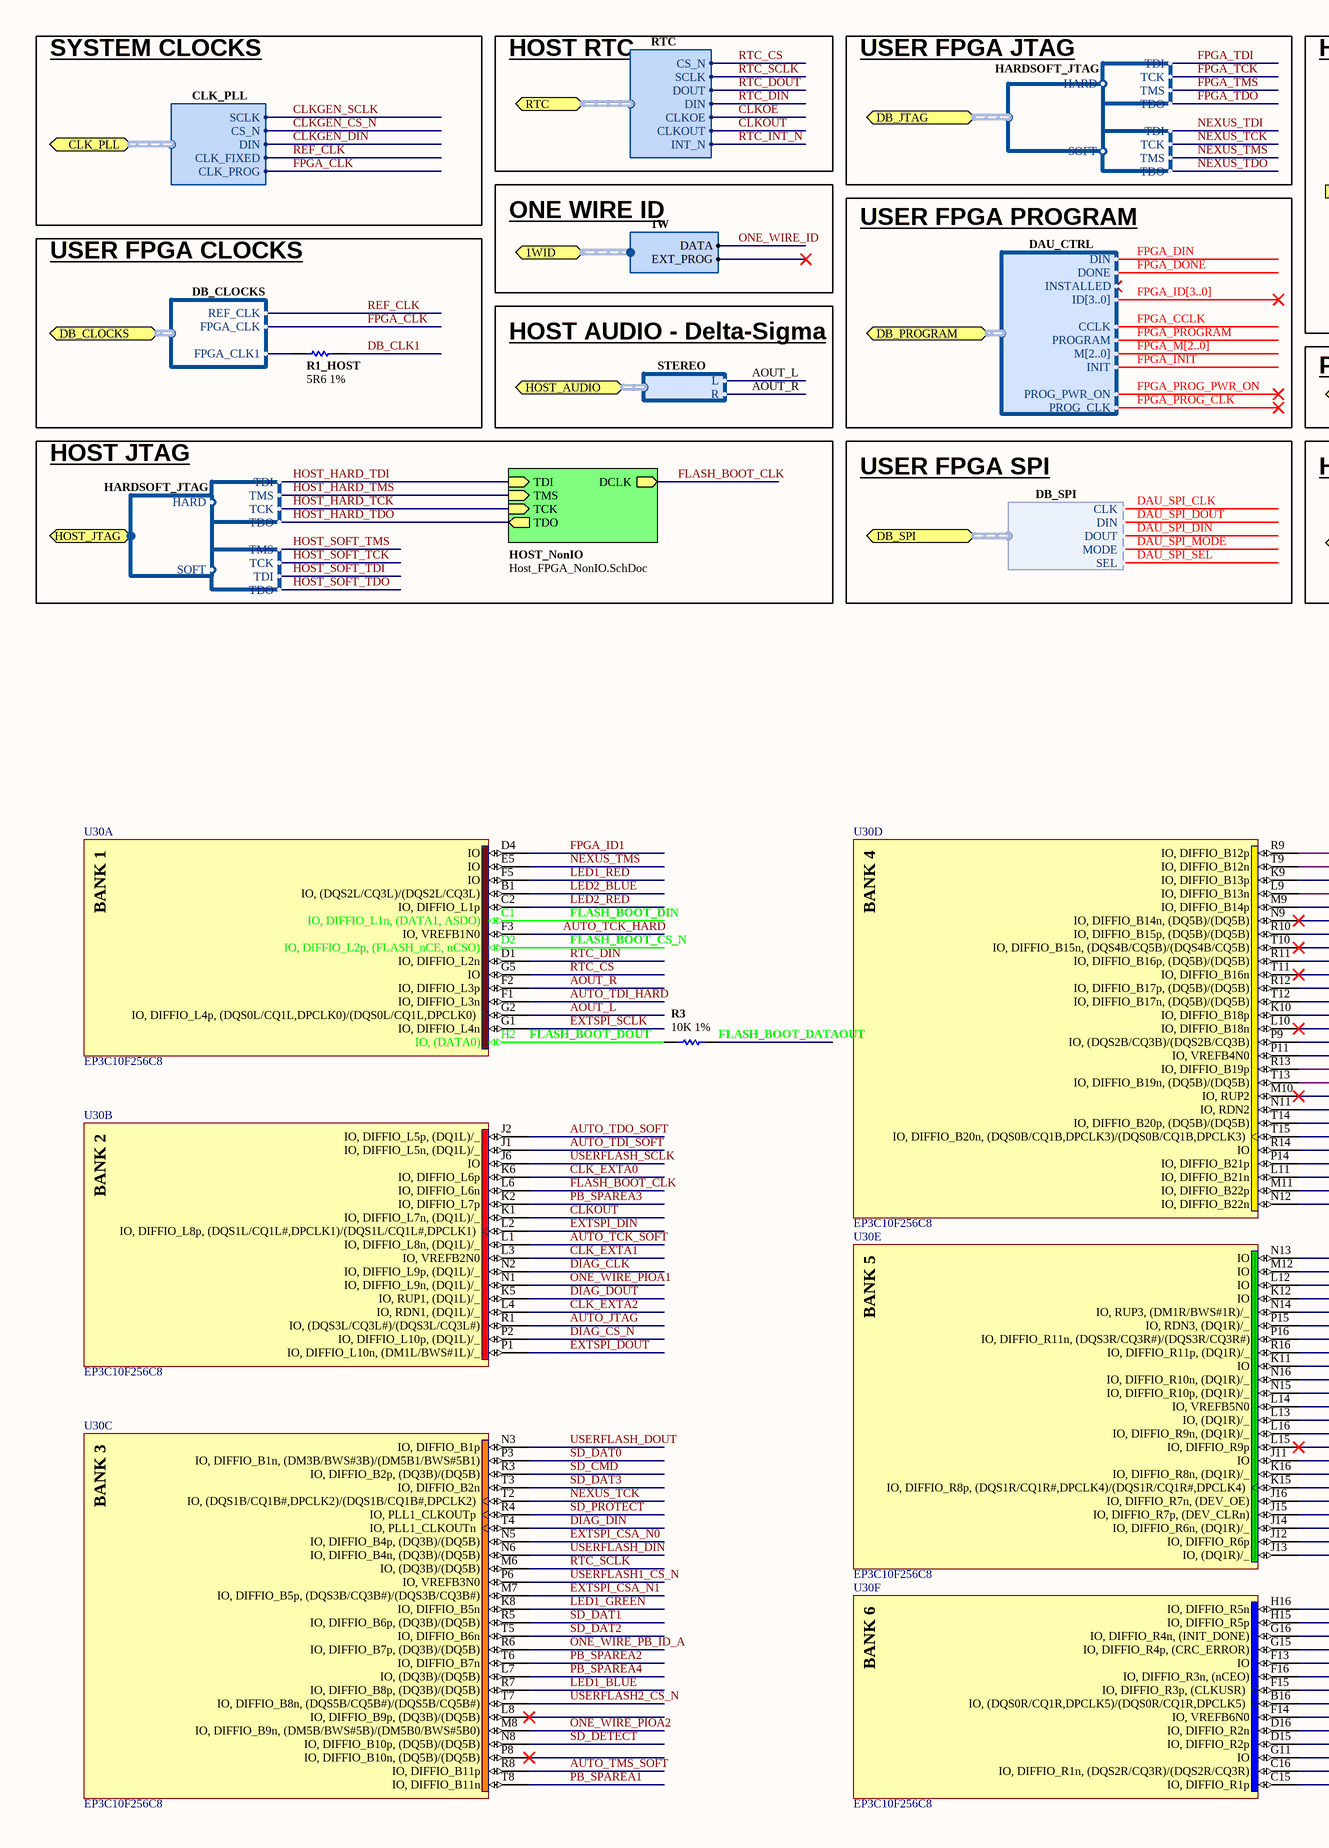
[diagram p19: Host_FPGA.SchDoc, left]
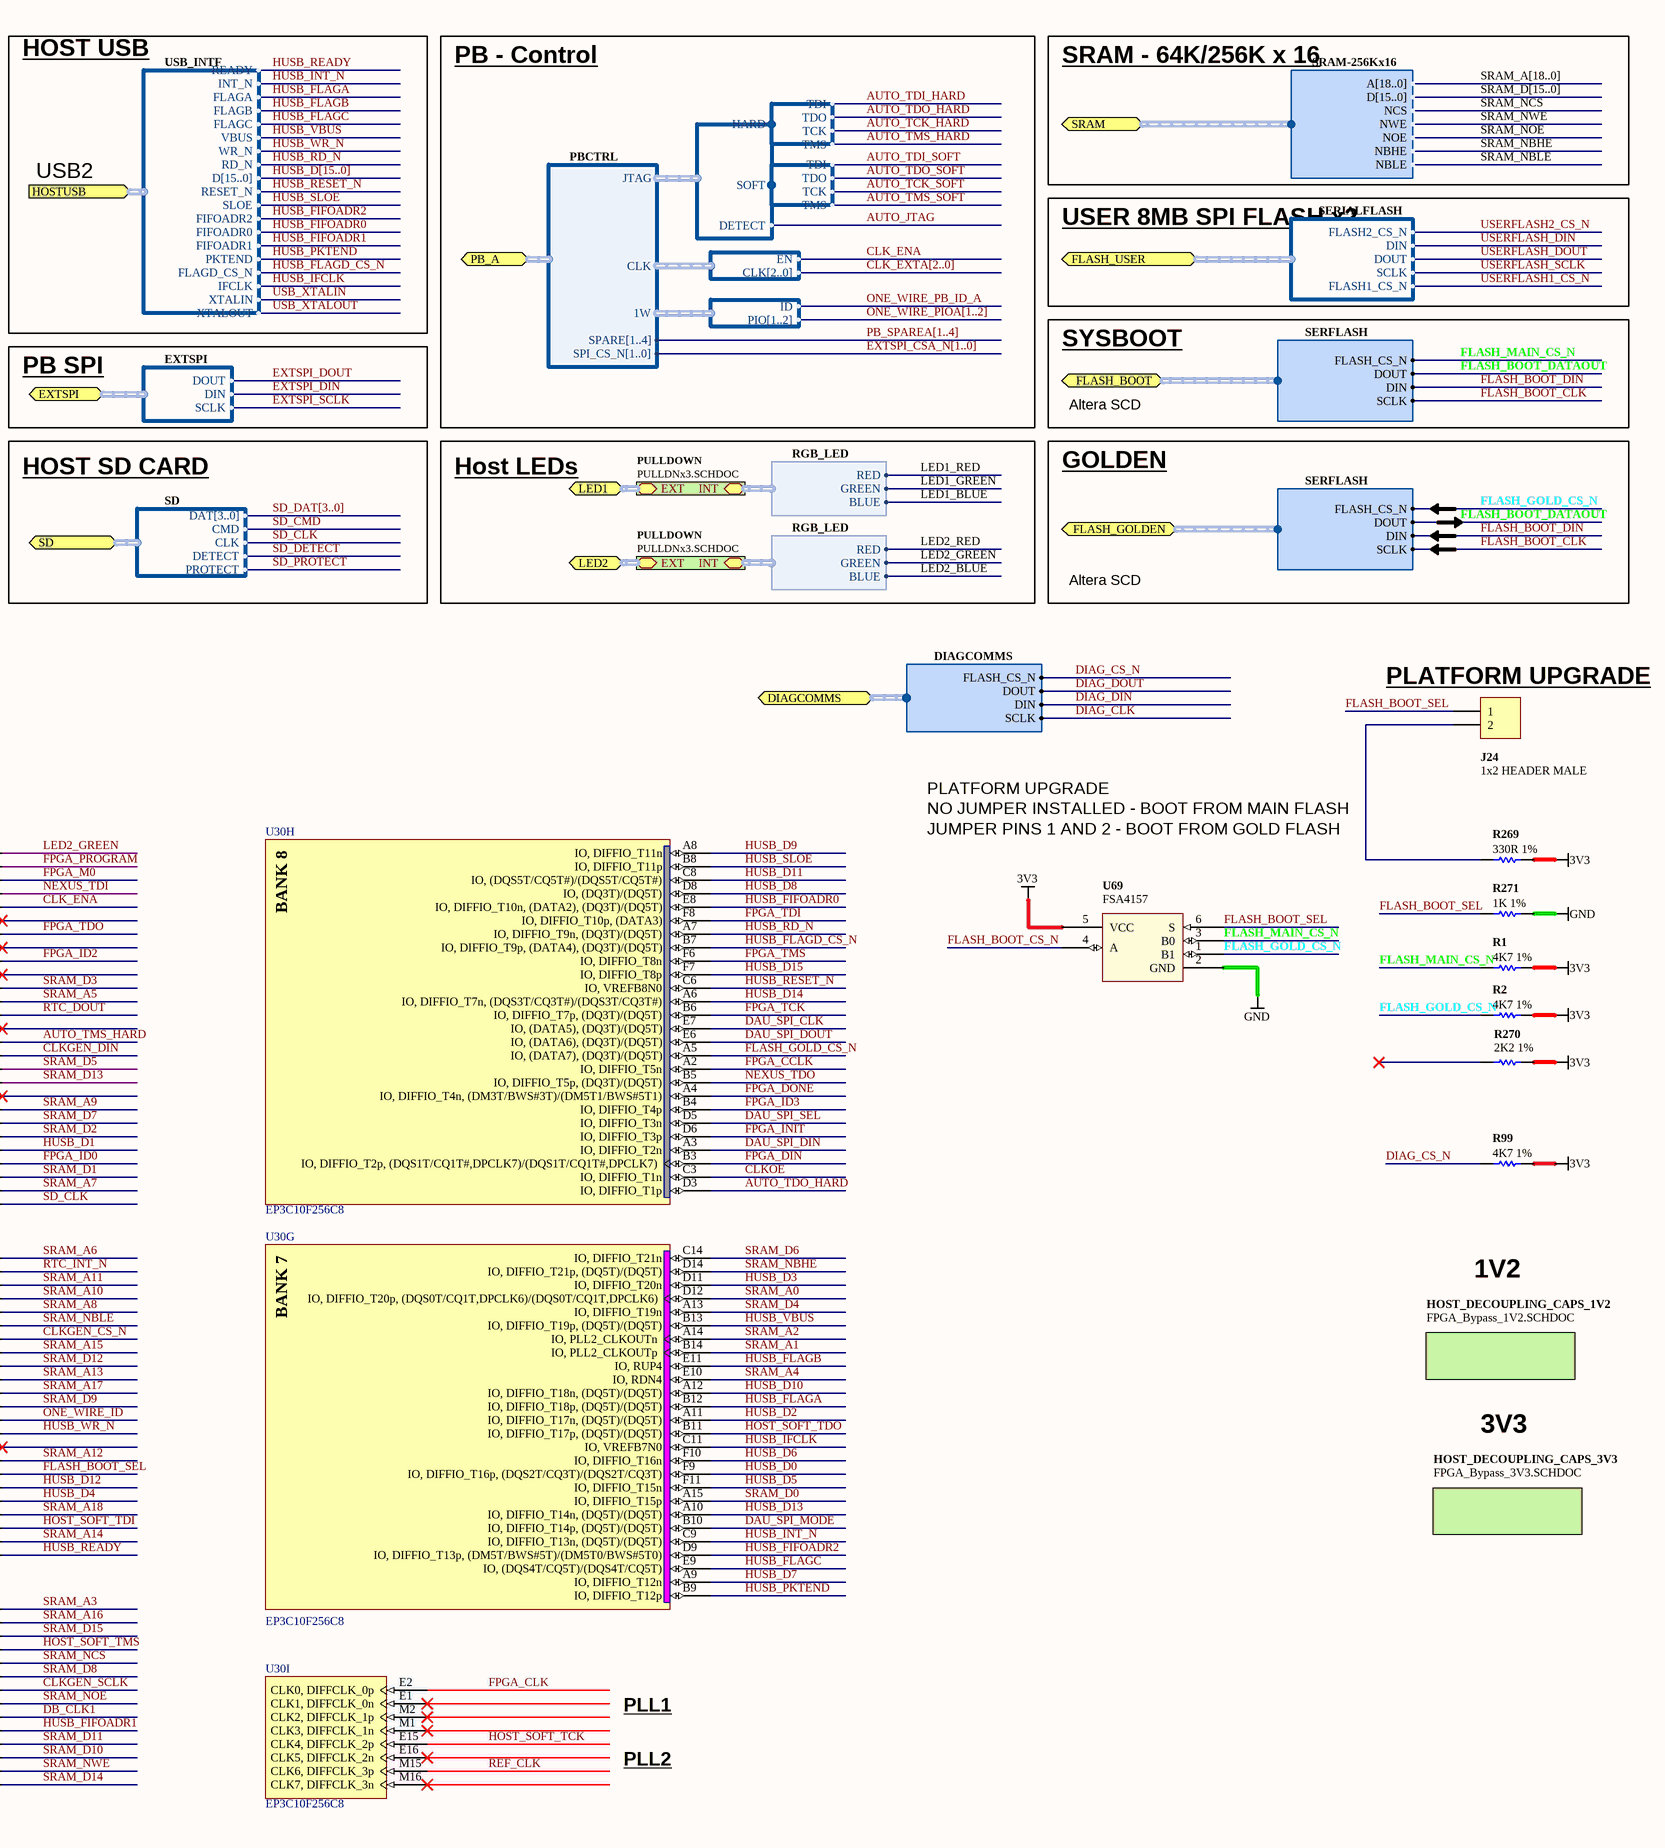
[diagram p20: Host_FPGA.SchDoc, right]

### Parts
(Parts that share a designator on the sheet are numbered #1, #2 ... from top to bottom, then left to right.)
J24  1x2 HEADER MALE  [HDR1X2]
R1#4  4K7 1%  [RESC1005-STAR]
R1_HOST  5R6 1%  [RESC1005-STAR]
R2#4  4K7 1%  [RESC1005-STAR]
R3#4  10K 1%  [RESC1005-STAR]
R99  4K7 1%  [RESC1005-STAR]
R269  330R 1%  [RESC1005-STAR]
R270  2K2 1%  [RESC1005-STAR]
R271  1K 1%  [RESC1005-STAR]
U30  EP3C10F256C8  [FBGA256-2]  (parts A,B,C,D,E,F,G,H,I of 13)
U69  FSA4157  [SC70_6L]

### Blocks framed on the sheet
USER FPGA CLOCKS: R1_HOST

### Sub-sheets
HOST_DECOUPLING_CAPS_1V2 = FPGA_Bypass_1V2.SCHDOC: no entries
HOST_DECOUPLING_CAPS_3V3 = FPGA_Bypass_3V3.SCHDOC: no entries
HOST_NonIO = Host_FPGA_NonIO.SchDoc: TMS (in), TCK (in), TDI (in), TDO (out), DCLK (out)
PULLDOWN = PULLDNx3.SCHDOC: EXT, INT (harness RGB_LED)
PULLDOWN = PULLDNx3.SCHDOC: EXT, INT (harness RGB_LED)

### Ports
1WID (harness 1W), CLK_PLL (harness CLK_PLL), DB_CLOCKS (harness DB_CLOCKS), DB_JTAG (harness HARDSOFT_JTAG), DB_PROGRAM (harness DAU_CTRL), DB_SPI (harness DB_SPI), DIAGCOMMS (harness DIAGCOMMS), EXTSPI (harness EXTSPI), FLASH_BOOT (harness SERFLASH), FLASH_GOLDEN (harness SERFLASH), FLASH_USER (harness SERIALFLASH), HOST_AUDIO (harness STEREO), HOST_JTAG (harness HARDSOFT_JTAG), HOSTUSB (harness USB_INTF), LED1 (harness RGB_LED), LED2 (harness RGB_LED), PB_A (harness PBCTRL), RTC (harness RTC), SD (harness SD), SRAM (harness SRAM-256Kx16)

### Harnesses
SERIALFLASH: FLASH2_CS_N, DIN, DOUT, SCLK, FLASH1_CS_N
JTAG: TMS, TDO, TDI, TCK
HARDSOFT_JTAG: HARD, SOFT
SD: DAT[3..0], CMD, CLK, DETECT, PROTECT
STEREO: L, R
RTC: CS_N, DIN, DOUT, INT_N, SCLK, CLKOUT, CLKOE
DAU_CTRL: DIN, DONE, INSTALLED, ID[3..0], CCLK, PROGRAM, M[2..0], INIT, PROG_PWR_ON, PROG_CLK
1W: DATA, EXT_PROG
CLK_PLL: CLK_FIXED, CLK_PROG, CS_N, DIN, SCLK
SRAM-256Kx16: A[18..0], D[15..0], NCS, NWE, NOE, NBHE, NBLE
RGB_LED: GREEN, RED, BLUE
DB_CLOCKS: REF_CLK, FPGA_CLK, FPGA_CLK1
DB_SPI: MODE, SEL, CLK, DIN, DOUT
JTAG_CONFIG: HARD, SOFT, DETECT
JTAG: TDI, TDO, TCK, TMS
GATE_CLOCKS: EN, CLK[2..0]
ONE_WIRE: ID, PIO[1..2]
PBCTRL: JTAG, CLK, 1W, SPI_CS_N[1..0], SPARE[1..4]
EXTSPI: DOUT, DIN, SCLK
SERFLASH: DIN, DOUT, SCLK, FLASH_CS_N
USB_INTF: READY, INT_N, SLOE, FIFOADR2, FIFOADR0, FIFOADR1, PKTEND, FLAGD_CS_N, FLAGA, FLAGB, FLAGC, WR_N, RD_N, D[15..0], RESET_N, IFCLK, XTALIN, VBUS, XTALOUT
DIAGCOMMS: DIN, DOUT, SCLK, FLASH_CS_N

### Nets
3V3: R1#4.2 R2#4.2 R99.2 R269.2 R270.2 U69.5(VCC)
GND: R271.2 U69.2(GND)
AOUT_L: U30.G2(IO,_DIFFIO_L4p,_(DQS0L/CQ1L,DPCLK0)/(DQS0L/CQ1L,DPCLK0)) ; port HOST_AUDIO.L
AOUT_R: U30.F2(IO,_DIFFIO_L3p) ; port HOST_AUDIO.R
AUTO_JTAG: U30.R1(IO,_(DQS3L/CQ3L#)/(DQS3L/CQ3L#)) ; harness JTAG_CONFIG.DETECT
AUTO_TCK_HARD: U30.F3(IO,_VREFB1N0) ; harness JTAG.TCK
AUTO_TCK_SOFT: U30.L1(IO,_DIFFIO_L8n,_(DQ1L)/_) ; harness JTAG.TCK
AUTO_TDI_HARD: U30.F1(IO,_DIFFIO_L3n) ; harness JTAG.TDI
AUTO_TDI_SOFT: U30.J1(IO,_DIFFIO_L5n,_(DQ1L)/_) ; harness JTAG.TDI
AUTO_TDO_HARD: U30.D3(IO,_DIFFIO_T1p) ; harness JTAG.TDO
AUTO_TDO_SOFT: U30.J2(IO,_DIFFIO_L5p,_(DQ1L)/_) ; harness JTAG.TDO
AUTO_TMS_HARD: U30.P9(IO,_(DQS2B/CQ3B)/(DQS2B/CQ3B)) ; harness JTAG.TMS
AUTO_TMS_SOFT: U30.R8(IO,_DIFFIO_B11p) ; harness JTAG.TMS
CLK_ENA: U30.M9(IO,_DIFFIO_B14p) ; harness GATE_CLOCKS.EN
CLK_EXTA0: U30.K6(IO,_DIFFIO_L6p)
CLK_EXTA1: U30.L3(IO,_VREFB2N0)
CLK_EXTA2: U30.L4(IO,_RDN1,_(DQ1L)/_)
CLKGEN_CS_N: U30.P16(IO,_DIFFIO_R11n,_(DQS3R/CQ3R#)/(DQS3R/CQ3R#)) ; port CLK_PLL.CS_N
CLKGEN_DIN: U30.P11(IO,_VREFB4N0) ; port CLK_PLL.DIN
CLKGEN_SCLK: U30.F15(IO,_DIFFIO_R3p,_(CLKUSR)) ; port CLK_PLL.SCLK
CLKOE: U30.C3(IO,_DIFFIO_T1n) ; port RTC.CLKOE
CLKOUT: U30.K1(IO,_DIFFIO_L7n,_(DQ1L)/_) ; port RTC.CLKOUT
DAU_SPI_CLK: U30.E7(IO,_(DATA5),_(DQ3T)/(DQ5T)) ; port DB_SPI.CLK
DAU_SPI_DIN: U30.A3(IO,_DIFFIO_T2n) ; port DB_SPI.DOUT
DAU_SPI_DOUT: U30.E6(IO,_(DATA6),_(DQ3T)/(DQ5T)) ; port DB_SPI.DIN
DAU_SPI_MODE: U30.B10(IO,_DIFFIO_T14p,_(DQ5T)/(DQ5T)) ; port DB_SPI.MODE
DAU_SPI_SEL: U30.D5(IO,_DIFFIO_T3n) ; port DB_SPI.SEL
DB_CLK1: R1_HOST.1 U30.F14(IO,_VREFB6N0)
DIAG_CLK: U30.N2(IO,_DIFFIO_L9p,_(DQ1L)/_) ; port DIAGCOMMS.SCLK
DIAG_CS_N: R99.1 U30.P2(IO,_DIFFIO_L10p,_(DQ1L)/_) ; port DIAGCOMMS.FLASH_CS_N
DIAG_DIN: U30.T4(IO,_PLL1_CLKOUTn) ; port DIAGCOMMS.DIN
DIAG_DOUT: U30.K5(IO,_RUP1,_(DQ1L)/_) ; port DIAGCOMMS.DOUT
EXTSPI_CSA_N0: U30.N5(IO,_DIFFIO_B4p,_(DQ3B)/(DQ5B))
EXTSPI_CSA_N1: U30.M7(IO,_DIFFIO_B5p,_(DQS3B/CQ3B#)/(DQS3B/CQ3B#))
EXTSPI_DIN: U30.L2(IO,_DIFFIO_L8p,_(DQS1L/CQ1L#,DPCLK1)/(DQS1L/CQ1L#,DPCLK1)) ; port EXTSPI.DIN
EXTSPI_DOUT: U30.P1(IO,_DIFFIO_L10n,_(DM1L/BWS#1L)/_) ; port EXTSPI.DOUT
EXTSPI_SCLK: U30.G1(IO,_DIFFIO_L4n) ; port EXTSPI.SCLK
FLASH_BOOT_CLK: U30.L6(IO,_DIFFIO_L6n) ; sheet HOST_NonIO/DCLK, port FLASH_BOOT.SCLK, port FLASH_GOLDEN.SCLK
FLASH_BOOT_CS_N: U30.D2(IO,_DIFFIO_L2p,_(FLASH_nCE,_nCSO)) U69.4(A)
FLASH_BOOT_DATAOUT: R3#4.2 ; port FLASH_BOOT.DOUT, port FLASH_GOLDEN.DOUT
FLASH_BOOT_DIN: U30.C1(IO,_DIFFIO_L1n,_(DATA1,_ASDO)) ; port FLASH_BOOT.DIN, port FLASH_GOLDEN.DIN
FLASH_BOOT_DOUT: R3#4.1 U30.H2(IO,_(DATA0))
FLASH_BOOT_SEL: J24.1 R271.1 U30.K16(IO,_DIFFIO_R8n,_(DQ1R)/_) U69.6(S)
FLASH_GOLD_CS_N: R2#4.1 U30.A5(IO,_(DATA7),_(DQ3T)/(DQ5T)) U69.1(B1) ; port FLASH_GOLDEN.FLASH_CS_N
FLASH_MAIN_CS_N: R1#4.1 U69.3(B0) ; port FLASH_BOOT.FLASH_CS_N
FPGA_CCLK: U30.A2(IO,_DIFFIO_T5n) ; port DB_PROGRAM.CCLK
FPGA_CLK: U30.E2(CLK0,_DIFFCLK_0p) ; port CLK_PLL.CLK_PROG, port DB_CLOCKS.FPGA_CLK
FPGA_DIN: U30.B3(IO,_DIFFIO_T2p,_(DQS1T/CQ1T#,DPCLK7)/(DQS1T/CQ1T#,DPCLK7)) ; port DB_PROGRAM.DIN
FPGA_DONE: U30.A4(IO,_DIFFIO_T4n,_(DM3T/BWS#3T)/(DM5T1/BWS#5T1)) ; port DB_PROGRAM.DONE
FPGA_ID0: U30.P14(IO,_DIFFIO_B21p)
FPGA_ID1: U30.D4(IO)
FPGA_ID2: U30.R11(IO,_DIFFIO_B16p,_(DQ5B)/(DQ5B))
FPGA_ID3: U30.B4(IO,_DIFFIO_T4p)
FPGA_INIT: U30.D6(IO,_DIFFIO_T3p) ; port DB_PROGRAM.INIT
FPGA_M0: U30.K9(IO,_DIFFIO_B13p)
FPGA_PROGRAM: U30.T9(IO,_DIFFIO_B12n) ; port DB_PROGRAM.PROGRAM
FPGA_TCK: U30.B6(IO,_DIFFIO_T7p,_(DQ3T)/(DQ5T)) ; harness JTAG.TCK
FPGA_TDI: U30.F8(IO,_DIFFIO_T10p,_(DATA3)) ; harness JTAG.TDI
FPGA_TDO: U30.R10(IO,_DIFFIO_B15p,_(DQ5B)/(DQ5B)) ; harness JTAG.TDO
FPGA_TMS: U30.F6(IO,_DIFFIO_T8n) ; harness JTAG.TMS
HOST_HARD_TCK: sheet HOST_NonIO/TCK, harness JTAG.TCK
HOST_HARD_TDI: sheet HOST_NonIO/TDI, harness JTAG.TDI
HOST_HARD_TDO: sheet HOST_NonIO/TDO, harness JTAG.TDO
HOST_HARD_TMS: sheet HOST_NonIO/TMS, harness JTAG.TMS
HOST_SOFT_TCK: U30.E15(CLK4,_DIFFCLK_2p) ; harness JTAG.TCK
HOST_SOFT_TDI: U30.J14(IO,_DIFFIO_R6n,_(DQ1R)/_) ; harness JTAG.TDI
HOST_SOFT_TDO: U30.B11(IO,_DIFFIO_T17p,_(DQ5T)/(DQ5T)) ; harness JTAG.TDO
HOST_SOFT_TMS: U30.G15(IO,_DIFFIO_R4p,_(CRC_ERROR)) ; harness JTAG.TMS
HUSB_D0: U30.F9(IO,_DIFFIO_T16p,_(DQS2T/CQ3T)/(DQS2T/CQ3T))
HUSB_D1: U30.R14(IO)
HUSB_D2: U30.A11(IO,_DIFFIO_T17n,_(DQ5T)/(DQ5T))
HUSB_D3: U30.D11(IO,_DIFFIO_T20n)
HUSB_D4: U30.J16(IO,_DIFFIO_R7n,_(DEV_OE))
HUSB_D5: U30.F11(IO,_DIFFIO_T15n)
HUSB_D6: U30.F10(IO,_DIFFIO_T16n)
HUSB_D7: U30.A9(IO,_DIFFIO_T12n)
HUSB_D8: U30.D8(IO,_(DQ3T)/(DQ5T))
HUSB_D9: U30.A8(IO,_DIFFIO_T11n)
HUSB_D10: U30.A12(IO,_DIFFIO_T18n,_(DQ5T)/(DQ5T))
HUSB_D11: U30.C8(IO,_(DQS5T/CQ5T#)/(DQS5T/CQ5T#))
HUSB_D12: U30.K15(IO,_DIFFIO_R8p,_(DQS1R/CQ1R#,DPCLK4)/(DQS1R/CQ1R#,DPCLK4))
HUSB_D13: U30.A10(IO,_DIFFIO_T14n,_(DQ5T)/(DQ5T))
HUSB_D14: U30.A6(IO,_DIFFIO_T7n,_(DQS3T/CQ3T#)/(DQS3T/CQ3T#))
HUSB_D15: U30.F7(IO,_DIFFIO_T8p)
HUSB_FIFOADR0: U30.E8(IO,_DIFFIO_T10n,_(DATA2),_(DQ3T)/(DQ5T)) ; port HOSTUSB.FIFOADR0
HUSB_FIFOADR1: U30.D16(IO,_DIFFIO_R2n) ; port HOSTUSB.FIFOADR1
HUSB_FIFOADR2: U30.D9(IO,_DIFFIO_T13p,_(DM5T/BWS#5T)/(DM5T0/BWS#5T0)) ; port HOSTUSB.FIFOADR2
HUSB_FLAGA: U30.B12(IO,_DIFFIO_T18p,_(DQ5T)/(DQ5T)) ; port HOSTUSB.FLAGA
HUSB_FLAGB: U30.E11(IO,_RUP4) ; port HOSTUSB.FLAGB
HUSB_FLAGC: U30.E9(IO,_(DQS4T/CQ5T)/(DQS4T/CQ5T)) ; port HOSTUSB.FLAGC
HUSB_FLAGD_CS_N: U30.B7(IO,_DIFFIO_T9p,_(DATA4),_(DQ3T)/(DQ5T)) ; port HOSTUSB.FLAGD_CS_N
HUSB_IFCLK: U30.C11(IO,_VREFB7N0) ; port HOSTUSB.IFCLK
HUSB_INT_N: U30.C9(IO,_DIFFIO_T13n,_(DQ5T)/(DQ5T)) ; port HOSTUSB.INT_N
HUSB_PKTEND: U30.B9(IO,_DIFFIO_T12p) ; port HOSTUSB.PKTEND
HUSB_RD_N: U30.A7(IO,_DIFFIO_T9n,_(DQ3T)/(DQ5T)) ; port HOSTUSB.RD_N
HUSB_READY: U30.J13(IO,_(DQ1R)/_) ; port HOSTUSB.READY
HUSB_RESET_N: U30.C6(IO,_VREFB8N0) ; port HOSTUSB.RESET_N
HUSB_SLOE: U30.B8(IO,_DIFFIO_T11p) ; port HOSTUSB.SLOE
HUSB_VBUS: U30.B13(IO,_DIFFIO_T19p,_(DQ5T)/(DQ5T)) ; port HOSTUSB.VBUS
HUSB_WR_N: U30.L16(IO,_DIFFIO_R9n,_(DQ1R)/_) ; port HOSTUSB.WR_N
LED1_BLUE: U30.R7(IO,_DIFFIO_B8p,_(DQ3B)/(DQ5B)) ; sheet PULLDOWN/INT.BLUE
LED1_GREEN: U30.K8(IO,_DIFFIO_B5n) ; sheet PULLDOWN/INT.GREEN
LED1_RED: U30.F5(IO) ; sheet PULLDOWN/INT.RED
LED2_BLUE: U30.B1(IO,_(DQS2L/CQ3L)/(DQS2L/CQ3L)) ; sheet PULLDOWN/INT.BLUE
LED2_GREEN: U30.R9(IO,_DIFFIO_B12p) ; sheet PULLDOWN/INT.GREEN
LED2_RED: U30.C2(IO,_DIFFIO_L1p) ; sheet PULLDOWN/INT.RED
NEXUS_TCK: U30.T2(IO,_(DQS1B/CQ1B#,DPCLK2)/(DQS1B/CQ1B#,DPCLK2)) ; harness JTAG.TCK
NEXUS_TDI: U30.L9(IO,_DIFFIO_B13n) ; harness JTAG.TDI
NEXUS_TDO: U30.B5(IO,_DIFFIO_T5p,_(DQ3T)/(DQ5T)) ; harness JTAG.TDO
NEXUS_TMS: U30.E5(IO) ; harness JTAG.TMS
ONE_WIRE_ID: U30.L13(IO,_(DQ1R)/_) ; port 1WID.DATA
ONE_WIRE_PB_ID_A: U30.R6(IO,_DIFFIO_B7p,_(DQ3B)/(DQ5B)) ; harness ONE_WIRE.ID
ONE_WIRE_PIOA1: U30.N1(IO,_DIFFIO_L9n,_(DQ1L)/_)
ONE_WIRE_PIOA2: U30.M8(IO,_DIFFIO_B9n,_(DM5B/BWS#5B)/(DM5B0/BWS#5B0))
PB_SPAREA1: U30.T8(IO,_DIFFIO_B11n)
PB_SPAREA2: U30.T6(IO,_DIFFIO_B7n)
PB_SPAREA3: U30.K2(IO,_DIFFIO_L7p)
PB_SPAREA4: U30.L7(IO,_(DQ3B)/(DQ5B))
REF_CLK: U30.M15(CLK6,_DIFFCLK_3p) ; port CLK_PLL.CLK_FIXED, port DB_CLOCKS.REF_CLK
RTC_CS: U30.G5(IO) ; port RTC.CS_N
RTC_DIN: U30.D1(IO,_DIFFIO_L2n) ; port RTC.DIN
RTC_DOUT: U30.K10(IO,_DIFFIO_B18p) ; port RTC.DOUT
RTC_INT_N: U30.M12(IO) ; port RTC.INT_N
RTC_SCLK: U30.M6(IO,_(DQ3B)/(DQ5B)) ; port RTC.SCLK
SD_CLK: U30.N12(IO,_DIFFIO_B22n) ; port SD.CLK
SD_CMD: U30.R3(IO,_DIFFIO_B2p,_(DQ3B)/(DQ5B)) ; port SD.CMD
SD_DAT0: U30.P3(IO,_DIFFIO_B1n,_(DM3B/BWS#3B)/(DM5B1/BWS#5B1))
SD_DAT1: U30.R5(IO,_DIFFIO_B6p,_(DQ3B)/(DQ5B))
SD_DAT2: U30.T5(IO,_DIFFIO_B6n)
SD_DAT3: U30.T3(IO,_DIFFIO_B2n)
SD_DETECT: U30.N8(IO,_DIFFIO_B10p,_(DQ5B)/(DQ5B)) ; port SD.DETECT
SD_PROTECT: U30.R4(IO,_PLL1_CLKOUTp) ; port SD.PROTECT
SRAM_A0: U30.D12(IO,_DIFFIO_T20p,_(DQS0T/CQ1T,DPCLK6)/(DQS0T/CQ1T,DPCLK6))
SRAM_A1: U30.B14(IO,_PLL2_CLKOUTp)
SRAM_A2: U30.A14(IO,_PLL2_CLKOUTn)
SRAM_A3: U30.H16(IO,_DIFFIO_R5n)
SRAM_A4: U30.E10(IO,_RDN4)
SRAM_A5: U30.T12(IO,_DIFFIO_B17n,_(DQ5B)/(DQ5B))
SRAM_A6: U30.N13(IO)
SRAM_A7: U30.M11(IO,_DIFFIO_B22p)
SRAM_A8: U30.N14(IO,_RUP3,_(DM1R/BWS#1R)/_)
SRAM_A9: U30.N11(IO,_RDN2)
SRAM_A10: U30.K12(IO)
SRAM_A11: U30.L12(IO)
SRAM_A12: U30.J11(IO)
SRAM_A13: U30.N16(IO,_DIFFIO_R10n,_(DQ1R)/_)
SRAM_A14: U30.J12(IO,_DIFFIO_R6p)
SRAM_A15: U30.R16(IO,_DIFFIO_R11p,_(DQ1R)/_)
SRAM_A16: U30.H15(IO,_DIFFIO_R5p)
SRAM_A17: U30.N15(IO,_DIFFIO_R10p,_(DQ1R)/_)
SRAM_A18: U30.J15(IO,_DIFFIO_R7p,_(DEV_CLRn))
SRAM_D0: U30.A15(IO,_DIFFIO_T15p)
SRAM_D1: U30.L11(IO,_DIFFIO_B21n)
SRAM_D2: U30.T15(IO,_DIFFIO_B20n,_(DQS0B/CQ1B,DPCLK3)/(DQS0B/CQ1B,DPCLK3))
SRAM_D3: U30.R12(IO,_DIFFIO_B17p,_(DQ5B)/(DQ5B))
SRAM_D4: U30.A13(IO,_DIFFIO_T19n)
SRAM_D5: U30.R13(IO,_DIFFIO_B19p)
SRAM_D6: U30.C14(IO,_DIFFIO_T21n)
SRAM_D7: U30.T14(IO,_DIFFIO_B20p,_(DQ5B)/(DQ5B))
SRAM_D8: U30.F16(IO,_DIFFIO_R3n,_(nCEO))
SRAM_D9: U30.L14(IO,_VREFB5N0)
SRAM_D10: U30.G11(IO)
SRAM_D11: U30.D15(IO,_DIFFIO_R2p)
SRAM_D12: U30.K11(IO)
SRAM_D13: U30.T13(IO,_DIFFIO_B19n,_(DQ5B)/(DQ5B))
SRAM_D14: U30.C15(IO,_DIFFIO_R1p)
SRAM_D15: U30.G16(IO,_DIFFIO_R4n,_(INIT_DONE))
SRAM_NBHE: U30.D14(IO,_DIFFIO_T21p,_(DQ5T)/(DQ5T)) ; port SRAM.NBHE
SRAM_NBLE: U30.P15(IO,_RDN3,_(DQ1R)/_) ; port SRAM.NBLE
SRAM_NCS: U30.F13(IO) ; port SRAM.NCS
SRAM_NOE: U30.B16(IO,_(DQS0R/CQ1R,DPCLK5)/(DQS0R/CQ1R,DPCLK5)) ; port SRAM.NOE
SRAM_NWE: U30.C16(IO,_DIFFIO_R1n,_(DQS2R/CQ3R)/(DQS2R/CQ3R)) ; port SRAM.NWE
USERFLASH1_CS_N: U30.P6(IO,_VREFB3N0) ; port FLASH_USER.FLASH1_CS_N
USERFLASH2_CS_N: U30.T7(IO,_DIFFIO_B8n,_(DQS5B/CQ5B#)/(DQS5B/CQ5B#)) ; port FLASH_USER.FLASH2_CS_N
USERFLASH_DIN: U30.N6(IO,_DIFFIO_B4n,_(DQ3B)/(DQ5B)) ; port FLASH_USER.DIN
USERFLASH_DOUT: U30.N3(IO,_DIFFIO_B1p) ; port FLASH_USER.DOUT
USERFLASH_SCLK: U30.J6(IO) ; port FLASH_USER.SCLK
NetJ24_2: J24.2 R269.1
NetR1_HOST_2: R1_HOST.2 ; port DB_CLOCKS.FPGA_CLK1

Not connected (* = marked no-connect by the designer): R270 1*; U30 E1(CLK1,_DIFFCLK_0n)* E16(CLK5,_DIFFCLK_2n)* L8(IO,_DIFFIO_B9p,_(DQ3B)/(DQ5B))* L10(IO,_DIFFIO_B18n)* L15(IO,_DIFFIO_R9p)* M1(CLK3,_DIFFCLK_1n)* M2(CLK2,_DIFFCLK_1p)* M10(IO,_RUP2)* M16(CLK7,_DIFFCLK_3n)* N9(IO,_DIFFIO_B14n,_(DQ5B)/(DQ5B))* P8(IO,_DIFFIO_B10n,_(DQ5B)/(DQ5B))* T10(IO,_DIFFIO_B15n,_(DQS4B/CQ5B)/(DQS4B/CQ5B))* T11(IO,_DIFFIO_B16n)*

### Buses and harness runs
bus CLK_EXTA[2..0]
bus EXTSPI_CSA_N[1..0]
bus FPGA_ID[3..0]
bus FPGA_M[2..0]
bus HUSB_D[15..0]
bus ONE_WIRE_PIOA[1..2]
bus PB_SPAREA[1..4]
bus SD_DAT[3..0]
bus SRAM_A[18..0]
bus SRAM_D[15..0]
harness port LED1 = sheet PULLDOWN/EXT
harness port LED2 = sheet PULLDOWN/EXT

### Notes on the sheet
- SYSTEM CLOCKS
- HOST RTC
- USER FPGA JTAG
- HOST USB
- PB - Control
- SRAM - 64K/256K x 16
- USB2
- ONE WIRE ID
- USER FPGA PROGRAM
- USER 8MB SPI FLASH x2
- HOST AUDIO - Delta-Sigma
- PB SPI
- SYSBOOT
- HOST JTAG
- Altera SCD
- USER FPGA SPI
- HOST SD CARD
- Host LEDs
- GOLDEN
- (near J24) PLATFORM UPGRADE
- PLATFORM UPGRADE
- NO JUMPER INSTALLED - BOOT FROM MAIN FLASH
- JUMPER PINS 1 AND 2 - BOOT FROM GOLD FLASH
- 1V2
- 3V3
- PLL1
- PLL2

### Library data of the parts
J24 = D-300-0020: Header IDC, 2 x 1 Pin Vertical 2.54mm Pitch (Non-Boxed, Male); Max Current: 3 A
R1#4 R2#4 R99 = D-100-0088: as R284-R286 on sheet PULLDNx3
R1_HOST = D-100-0085: Resistor, 5R6 1% 0402 (1005); Power Rating: 63 mW; Resistance: 5.6 R
R3#4 = D-100-0130: Resistor, 10K 1% 0402 (1005); Power Rating: 63 mW
R269 = D-100-0121: UPDATE FROM UL LIBRARIES; Power Rating: 63 mW; Resistance: 1 K
R270 = D-100-0107: Resistor, 2K2 1% 0402 (1005); Power Rating: 63 mW; Resistance: 2.2 K
R271 = D-100-0130: UPDATE FROM UL LIBRARIES; Power Rating: 63 mW; Resistance: 10 K
U30 = EP3C10F256C8: Cyclone III Family FPGA, 182 I/O Pins, 4 PLLs, 256-Pin FBGA, Speed Grade 8, Commercial Grade
U69 = D-200-0006: Low Voltage 1R  SPDT Analog Switc; Supply Voltage: mV

## Sheet HOST_FPGA_NonIO.SchDoc: Host FPGA Pwr and Programming
size A4; Organization: Altium Limited.
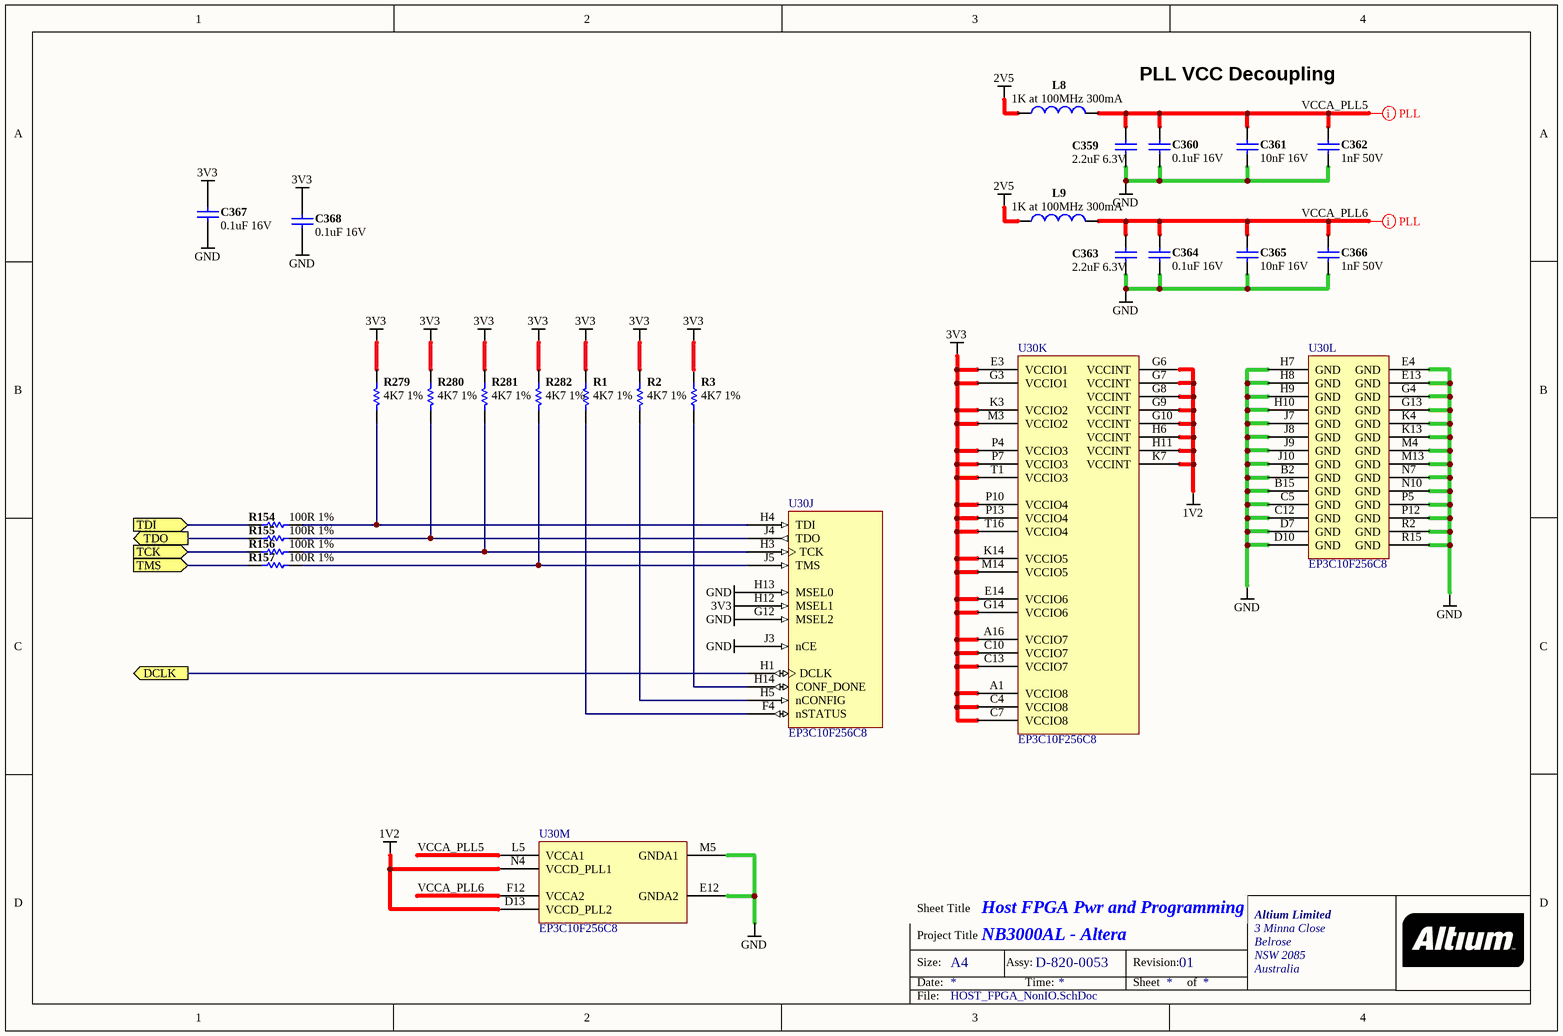
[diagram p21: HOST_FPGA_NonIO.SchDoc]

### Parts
(Parts that share a designator on the sheet are numbered #1, #2 ... from top to bottom, then left to right.)
C359  2.2uF 6.3V  [CAPC1005-STAR]
C360  0.1uF 16V  [CAPC1005-STAR]
C361  10nF 16V  [CAPC1005-STAR]
C362  1nF 50V  [CAPC1005-STAR]
C363  2.2uF 6.3V  [CAPC1005-STAR]
C364  0.1uF 16V  [CAPC1005-STAR]
C365  10nF 16V  [CAPC1005-STAR]
C366  1nF 50V  [CAPC1005-STAR]
C367  0.1uF 16V  [CAPC1005-STAR]
C368  0.1uF 16V  [CAPC1005-STAR]
L8  1K at 100MHz 300mA  [INDC1005]
L9  1K at 100MHz 300mA  [INDC1005]
R1#5  4K7 1%  [RESC1005-STAR]
R2#5  4K7 1%  [RESC1005-STAR]
R3#5  4K7 1%  [RESC1005-STAR]
R154#2  100R 1%  [RESC1005-STAR]
R155  100R 1%  [RESC1005-STAR]
R156  100R 1%  [RESC1005-STAR]
R157  100R 1%  [RESC1005-STAR]
R279  4K7 1%  [RESC1005-STAR]
R280  4K7 1%  [RESC1005-STAR]
R281  4K7 1%  [RESC1005-STAR]
R282  4K7 1%  [RESC1005-STAR]
U30  EP3C10F256C8  [FBGA256-2]  (parts J,K,L,M of 13)

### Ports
DCLK (out), TCK (in), TDI (in), TDO (out), TMS (in)

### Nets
1V2: U30.D13(VCCD_PLL2) U30.G6(VCCINT) U30.G7(VCCINT) U30.G8(VCCINT) U30.G9(VCCINT) U30.G10(VCCINT) U30.H6(VCCINT) U30.H11(VCCINT) U30.K7(VCCINT) U30.N4(VCCD_PLL1)
2V5: L8.1 L9.1
3V3: C367.1 C368.1 R1#5.1 R2#5.1 R3#5.1 R279.1 R280.1 R281.1 R282.1 U30.A1(VCCIO8) U30.A16(VCCIO7) U30.C4(VCCIO8) U30.C7(VCCIO8) U30.C10(VCCIO7) U30.C13(VCCIO7) U30.E3(VCCIO1) U30.E14(VCCIO6) U30.G3(VCCIO1) U30.G14(VCCIO6) U30.H12(MSEL1) U30.K3(VCCIO2) U30.K14(VCCIO5) U30.M3(VCCIO2) U30.M14(VCCIO5) U30.P4(VCCIO3) U30.P7(VCCIO3) U30.P10(VCCIO4) U30.P13(VCCIO4) U30.T1(VCCIO3) U30.T16(VCCIO4)
GND: C359.2 C360.2 C361.2 C362.2 C363.2 C364.2 C365.2 C366.2 C367.2 C368.2 U30.B2(GND) U30.B15(GND) U30.C5(GND) U30.C12(GND) U30.D7(GND) U30.D10(GND) U30.E4(GND) U30.E12(GNDA2) U30.E13(GND) U30.G4(GND) U30.G12(MSEL2) U30.G13(GND) U30.H7(GND) U30.H8(GND) U30.H9(GND) U30.H10(GND) U30.H13(MSEL0) U30.J3(nCE) U30.J7(GND) U30.J8(GND) U30.J9(GND) U30.J10(GND) U30.K4(GND) U30.K13(GND) U30.M4(GND) U30.M5(GNDA1) U30.M13(GND) U30.N7(GND) U30.N10(GND) U30.P5(GND) U30.P12(GND) U30.R2(GND) U30.R15(GND)
FLASH_BOOT_CLK: U30.H1(DCLK) ; port DCLK
HOST_HARD_TCK: R156.1 ; port TCK
HOST_HARD_TDI: R154#2.1 ; port TDI
HOST_HARD_TDO: R155.1 ; port TDO
HOST_HARD_TMS: R157.1 ; port TMS
VCCA_PLL5: C359.1 C360.1 C361.1 C362.1 L8.2 U30.L5(VCCA1)
VCCA_PLL6: C363.1 C364.1 C365.1 C366.1 L9.2 U30.F12(VCCA2)
NetR1#5_2: R1#5.2 U30.F4(nSTATUS)
NetR2#5_2: R2#5.2 U30.H5(nCONFIG)
NetR3#5_2: R3#5.2 U30.H14(CONF_DONE)
NetR154#2_2: R154#2.2 R279.2 U30.H4(TDI)
NetR155_2: R155.2 R280.2 U30.J4(TDO)
NetR156_2: R156.2 R281.2 U30.H3(TCK)
NetR157_2: R157.2 R282.2 U30.J5(TMS)

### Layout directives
net class PLL: VCCA_PLL5, VCCA_PLL6

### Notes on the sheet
- PLL VCC Decoupling

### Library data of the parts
C359 C363 = D-101-0112: as C343 on sheet FPGA_NonIO
C360 C364 C367 C368 = D-101-0080: as C46_FP on sheet FPGA_Bypass_3V3
C361 C365 = D-101-0077: as C62_FP on sheet FPGA_Bypass_3V3
C362 C366 = D-101-0030: as C346 on sheet FPGA_NonIO
L8 L9 = D-102-0026: as L4 on sheet FPGA_NonIO
R1#5 R2#5 R3#5 R279-R282 = D-100-0088: as R284-R286 on sheet PULLDNx3
R154#2 R155-R157 = D-100-0131: Resistor, 100R 1% 0402 (1005); Power Rating: 63 mW
U30 = EP3C10F256C8: as U30 on sheet Host_FPGA

## Sheet TSC_XPT2046.SchDoc: TFT Touchscreen Interface
size A4; Organization: Altium Limited.; Address1: Level 3, 12a Rodborough Rd; Address2: Frenchs Forest 2086; Address3: NSW; Address4: AUSTRALIA; DocumentNumber: 31; SheetNumber: 32; SheetTotal: 78
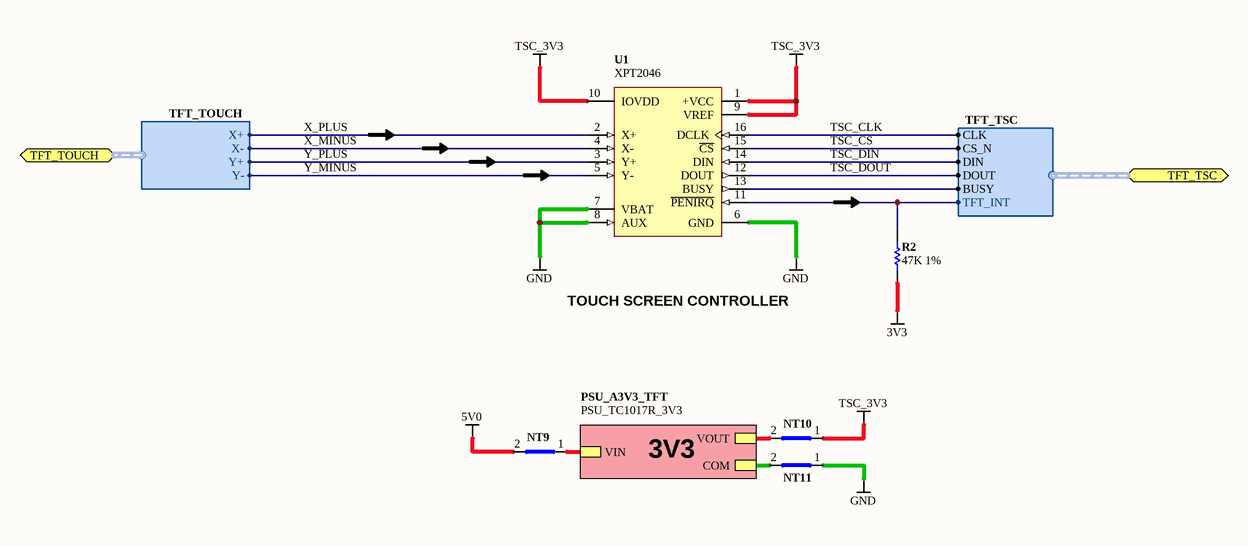
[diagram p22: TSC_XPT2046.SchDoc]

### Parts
(Parts that share a designator on the sheet are numbered #1, #2 ... from top to bottom, then left to right.)
NT9  Net Tie SMT2  [NETTIE-SMT2-31X51]  (value not drawn)  (net tie, no BOM)
NT10  Net Tie SMT2  [NETTIE-SMT2-31X51]  (value not drawn)  (net tie, no BOM)
NT11#2  Net Tie SMT2  [NETTIE-SMT2-31X51]  (value not drawn)  (net tie, no BOM)
R2#6  47K 1%  [RESC1005-STAR]
U1#4  XPT2046  [TSOP65P640-16AN]

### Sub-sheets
PSU_A3V3_TFT = PSU_TC1017R_3V3 (file not in this document): VIN, VOUT, COM

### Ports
TFT_TOUCH (harness TFT_TOUCH), TFT_TSC (harness TFT_TSC)

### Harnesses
TFT_TSC: CLK, CS_N, DIN, DOUT, BUSY, TFT_INT
TFT_TOUCH: X+, X-, Y+, Y-

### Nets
3V3: R2#6.1
5V0: NT9.2(Net2)
GND: NT11#2.1(Net1) U1#4.6(GND) U1#4.7(VBAT) U1#4.8(AUX)
TSC_3V3: NT10.1(Net1) U1#4.1(+VCC) U1#4.9(VREF) U1#4.10(IOVDD)
TSC_CLK: U1#4.16(DCLK) ; port TFT_TSC.CLK
TSC_CS: U1#4.15(~{CS}) ; port TFT_TSC.CS_N
TSC_DIN: U1#4.14(DIN) ; port TFT_TSC.DIN
TSC_DOUT: U1#4.12(DOUT) ; port TFT_TSC.DOUT
X_MINUS: U1#4.4(X-) ; port TFT_TOUCH.X-
X_PLUS: U1#4.2(X+) ; port TFT_TOUCH.X+
Y_MINUS: U1#4.5(Y-) ; port TFT_TOUCH.Y-
Y_PLUS: U1#4.3(Y+) ; port TFT_TOUCH.Y+
NetNT9_1: NT9.1(Net1) ; sheet PSU_A3V3_TFT/VIN
NetNT10_2: NT10.2(Net2) ; sheet PSU_A3V3_TFT/VOUT
NetNT11#2_2: NT11#2.2(Net2) ; sheet PSU_A3V3_TFT/COM
NetR2#6_2: R2#6.2 U1#4.11(~{PENIRQ}) ; port TFT_TSC.TFT_INT
NetU1#4_13: U1#4.13(BUSY) ; port TFT_TSC.BUSY

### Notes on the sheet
- TOUCH SCREEN CONTROLLER
- 3V3

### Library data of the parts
NT9 NT10 NT11#2 = D-002-0003: Net-Tie, Surface Mount, 2 x 1.6mm x 0.8mm SMT Pads - For 0.8mm Track
R2#6 = D-100-0092: Resistor, 47K 1% 0402 (1005); Power Rating: 63 mW
U1#4 = D-202-0006: XPT2046, Touch Screen Controller; Supply Voltage: 2.7 to 5.5 V

## Sheet USB_CY7C68001-56LFC.SchDoc: High-Speed USB 2.0 Controller
size A4; Organization: Altium Limited.; Address1: Level 3, 12a Rodborough Rd; Address2: Frenchs Forest 2086; Address3: NSW; Address4: AUSTRALIA; DocumentNumber: 49; SheetNumber: 50; SheetTotal: 78
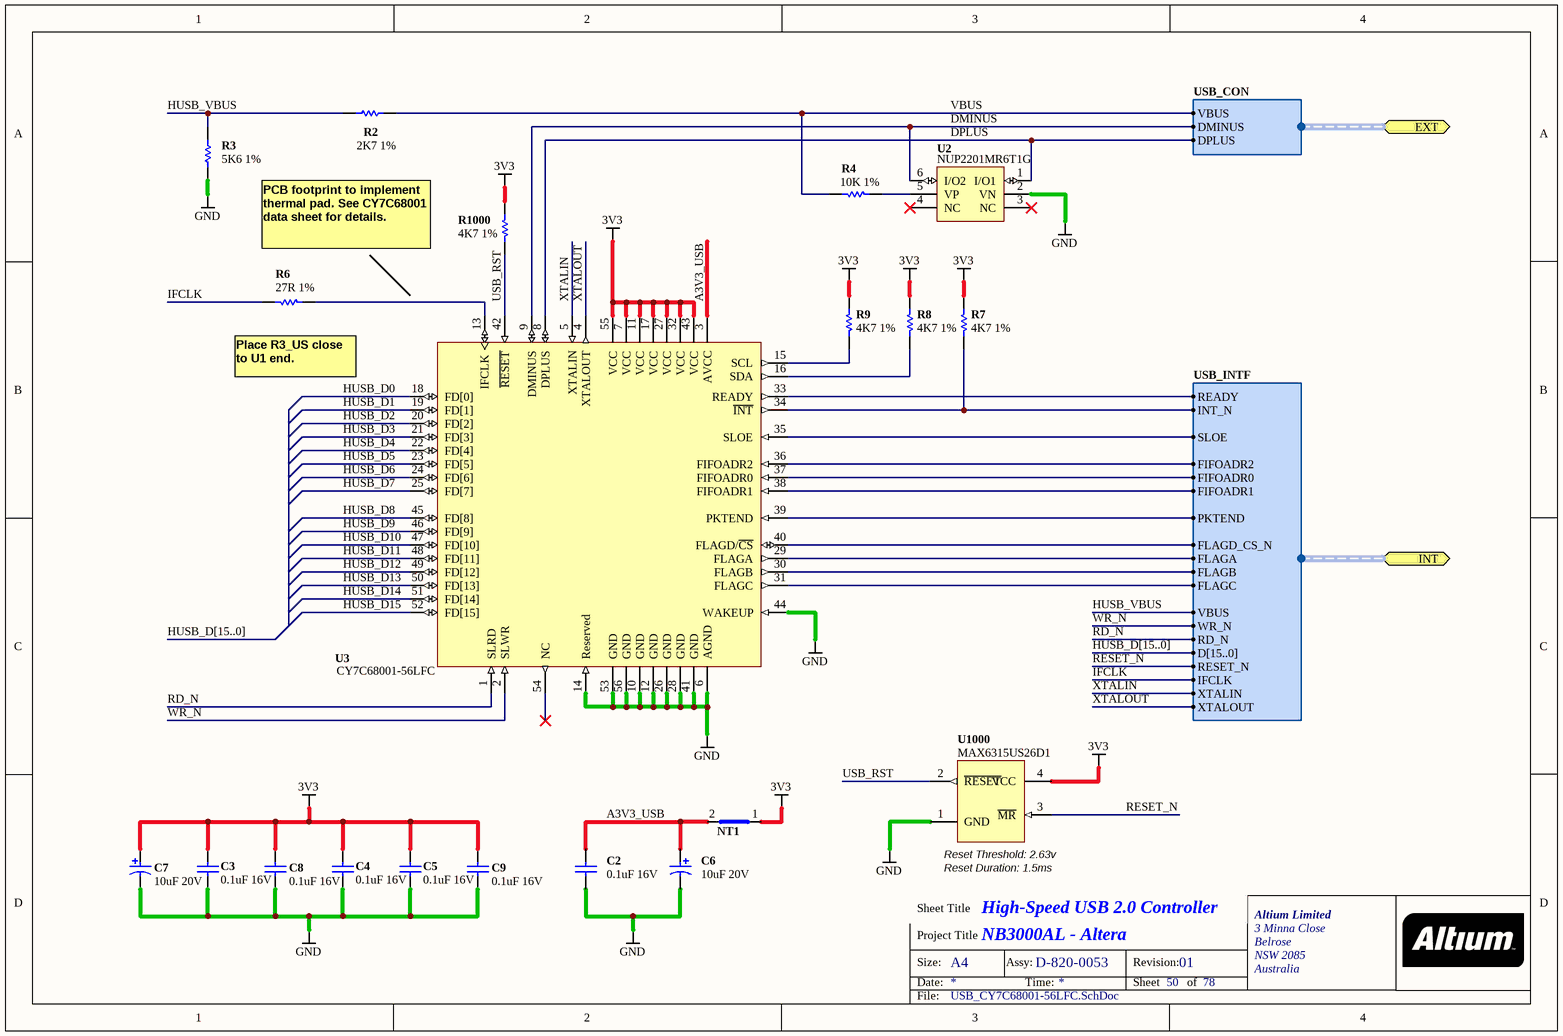
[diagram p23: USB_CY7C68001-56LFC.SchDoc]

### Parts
(Parts that share a designator on the sheet are numbered #1, #2 ... from top to bottom, then left to right.)
C2#4  0.1uF 16V  [CAPC1005-STAR]
C3#4  0.1uF 16V  [CAPC1005-STAR]
C4#4  0.1uF 16V  [CAPC1005-STAR]
C5#3  0.1uF 16V  [CAPC1005-STAR]
C6#2  10uF 20V  [CAPC3528-STAR]
C7#2  10uF 20V  [CAPC3528-STAR]
C8#2  0.1uF 16V  [CAPC1005-STAR]
C9#2  0.1uF 16V  [CAPC1005-STAR]
NT1#3  Net Tie SMT2  [NETTIE-SMT2-31X51]  (value not drawn)  (net tie, no BOM)
R2#7  2K7 1%  [RESC1005-STAR]
R3#6  5K6 1%  [RESC1005-STAR]
R4#4  10K 1%  [RESC1005-STAR]
R6#3  27R 1%  [RESC1005-STAR]
R7#3  4K7 1%  [RESC1005-STAR]
R8#3  4K7 1%  [RESC1005-STAR]
R9#3  4K7 1%  [RESC1005-STAR]
R1000  4K7 1%  [RESC1005-STAR]
U2#2  NUP2201MR6T1G  [TSOP95P275-6]
U3  CY7C68001-56LFC  [QFN50P800X800_HS-57]
U1000  MAX6315US26D1  [SOT143]

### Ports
EXT (harness USB_CON), INT (harness USB_INTF)

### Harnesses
USB_INTF: READY, INT_N, SLOE, FIFOADR2, FIFOADR0, FIFOADR1, PKTEND, FLAGD_CS_N, FLAGA, FLAGB, FLAGC, WR_N, RD_N, D[15..0], RESET_N, IFCLK, XTALIN, VBUS, XTALOUT
USB_CON: VBUS, DMINUS, DPLUS

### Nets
3V3: C3#4.2 C4#4.2 C5#3.2 C7#2.1 C8#2.1 C9#2.1 NT1#3.1(Net1) R7#3.2 R8#3.1 R9#3.1 R1000.2 U3.7(VCC) U3.11(VCC) U3.17(VCC) U3.27(VCC) U3.32(VCC) U3.43(VCC) U3.55(VCC) U1000.4(VCC)
GND: C2#4.1 C3#4.1 C4#4.1 C5#3.1 C6#2.2 C7#2.2 C8#2.2 C9#2.2 R3#6.2 U2#2.2(VN) U3.6(AGND) U3.10(GND) U3.12(GND) U3.14(Reserved) U3.26(GND) U3.28(GND) U3.41(GND) U3.44(WAKEUP) U3.53(GND) U3.56(GND) U1000.1(GND)
A3V3_USB: C2#4.2 C6#2.1 NT1#3.2(Net2) U3.3(AVCC)
DMINUS: U2#2.6(I/O2) U3.9(DMINUS) ; port EXT.DMINUS
DPLUS: U2#2.1(I/O1) U3.8(DPLUS) ; port EXT.DPLUS
HUSB_D0: U3.18(FD[0])
HUSB_D1: U3.19(FD[1])
HUSB_D2: U3.20(FD[2])
HUSB_D3: U3.21(FD[3])
HUSB_D4: U3.22(FD[4])
HUSB_D5: U3.23(FD[5])
HUSB_D6: U3.24(FD[6])
HUSB_D7: U3.25(FD[7])
HUSB_D8: U3.45(FD[8])
HUSB_D9: U3.46(FD[9])
HUSB_D10: U3.47(FD[10])
HUSB_D11: U3.48(FD[11])
HUSB_D12: U3.49(FD[12])
HUSB_D13: U3.50(FD[13])
HUSB_D14: U3.51(FD[14])
HUSB_D15: U3.52(FD[15])
HUSB_VBUS: R2#7.1 R3#6.1 ; port INT.VBUS
IFCLK: R6#3.1 ; port INT.IFCLK
RD_N: U3.1(SLRD) ; port INT.RD_N
RESET_N: U1000.3(~{MR}) ; port INT.RESET_N
USB_RST: R1000.1 U3.42(~{RESET}) U1000.2(~{RESET})
VBUS: R2#7.2 R4#4.1 ; port EXT.VBUS
WR_N: U3.2(SLWR) ; port INT.WR_N
XTALIN: U3.5(XTALIN) ; port INT.XTALIN
XTALOUT: U3.4(XTALOUT) ; port INT.XTALOUT
NetR4#4_2: R4#4.2 U2#2.5(VP)
NetR6#3_2: R6#3.2 U3.13(IFCLK)
NetR7#3_1: R7#3.1 U3.34(~{INT}) ; port INT.INT_N
NetR8#3_2: R8#3.2 U3.16(SDA)
NetR9#3_2: R9#3.2 U3.15(SCL)
NetU3_29: U3.29(FLAGA) ; port INT.FLAGA
NetU3_30: U3.30(FLAGB) ; port INT.FLAGB
NetU3_31: U3.31(FLAGC) ; port INT.FLAGC
NetU3_33: U3.33(READY) ; port INT.READY
NetU3_35: U3.35(SLOE) ; port INT.SLOE
NetU3_36: U3.36(FIFOADR2) ; port INT.FIFOADR2
NetU3_37: U3.37(FIFOADR0) ; port INT.FIFOADR0
NetU3_38: U3.38(FIFOADR1) ; port INT.FIFOADR1
NetU3_39: U3.39(PKTEND) ; port INT.PKTEND
NetU3_40: U3.40(FLAGD/~{CS}) ; port INT.FLAGD_CS_N

Not connected (* = marked no-connect by the designer): U2#2 3(NC)* 4(NC)*; U3 54(NC)*

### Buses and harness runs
bus HUSB_D[15..0]

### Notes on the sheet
- PCB footprint to implement thermal pad. See CY7C68001 data sheet for details.
- (near R6#3) Place R3_US close to U1 end.
- (near U1000) Reset Threshold: 2.63v
- (near U1000) Reset Duration: 1.5ms

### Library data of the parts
C2#4 C3#4 C4#4 C5#3 C8#2 C9#2 = D-101-0080: as C46_FP on sheet FPGA_Bypass_3V3
C6#2 C7#2 = D-101-0007: as C38_FP on sheet FPGA_Bypass_3V3
NT1#3 = D-002-0003: as NT9 on sheet TSC_XPT2046
R2#7 = D-100-0105: Resistor, 2K7 1% 0402 (1005); Power Rating: 63 mW; Resistance: 2.7 K
R3#6 = D-100-0086: Resistor, 5K6 1% 0402 (1005); Power Rating: 63 mW; Resistance: 5.6 K
R4#4 = D-100-0130: as R3#4 on sheet Host_FPGA
R6#3 = D-100-0108: Resistor, 27R 1% 0402 (1005); Power Rating: 63 mW
R7#3 R8#3 R9#3 R1000 = D-100-0088: as R284-R286 on sheet PULLDNx3
U2#2 = D-204-0001: NUP2201MR6, Low Capacitance Diode Array, USB Protection; Max Input Voltage: mV; Max Output Current: mA
U3 = D-221-0004: CY7C68001-56LFC, EZ-USB SX2 High-Speed USB Interface; Comm Standard: None
U1000 = D-243-0000: MAX6315, Open-Drain Output SOT Reset IC, Customized Reset Thresholds, Timeout Delays

## Sheet OSC_24MHZ.SchDoc: 24MHz Oscillator
size A4; Organization: Altium Limited.
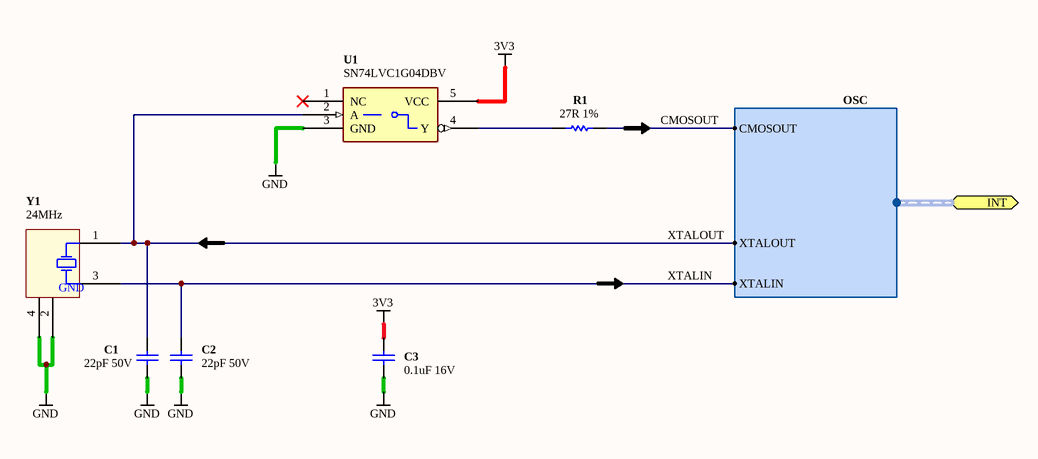
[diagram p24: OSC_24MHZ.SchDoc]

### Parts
(Parts that share a designator on the sheet are numbered #1, #2 ... from top to bottom, then left to right.)
C1#4  22pF 50V  [CAPC1005-STAR]
C2#5  22pF 50V  [CAPC1005-STAR]
C3#5  0.1uF 16V  [CAPC1005-STAR]
R1#6  27R 1%  [RESC1005-STAR]
U1#5  SN74LVC1G04DBV  [SOT95P280-5]
Y1#2  24MHz  [XTAL-200X126-4]

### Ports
INT (harness OSC)

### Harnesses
OSC: CMOSOUT, XTALIN, XTALOUT

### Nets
3V3: C3#5.1 U1#5.5(VCC)
GND: C1#4.2 C2#5.2 C3#5.2 U1#5.3(GND) Y1#2.2(GND) Y1#2.4(GND)
CMOSOUT: R1#6.1 ; port INT.CMOSOUT
XTALIN: C2#5.1 Y1#2.3(X2) ; port INT.XTALIN
XTALOUT: C1#4.1 U1#5.2(A) Y1#2.1(X1) ; port INT.XTALOUT
NetR1#6_2: R1#6.2 U1#5.4(Y)

Not connected (* = marked no-connect by the designer): U1#5 1(NC)*

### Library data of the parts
C1#4 C2#5 = D-101-0059: as C6#1 on sheet Ethernet_RTL8201CL
C3#5 = D-101-0080: as C46_FP on sheet FPGA_Bypass_3V3
R1#6 = D-100-0108: as R6#3 on sheet USB_CY7C68001-56LFC
U1#5 = D-205-0001: SN74LVC1G04DBV, Single Inverter Gate, 1.65-V to 5.5-V
Y1#2 = D-103-0013: Crystal, SMD, 24.000000MHz Stab=30ppm 20.0pF; Frequency Stability: 30 ppm; Load Capacitance: 20 pF; Nominal Operational Voltage: mV

## Sheet CON_AUDIO_AC99_NOMIC.SchDoc: AUDIO AC99 Interface
size A4; Organization: Altium Limited.; Address1: Level 3, 12a Rodborough Rd; Address2: Frenchs Forest 2086; Address3: NSW; Address4: AUSTRALIA; DocumentNumber: 59; SheetNumber: 60; SheetTotal: 78
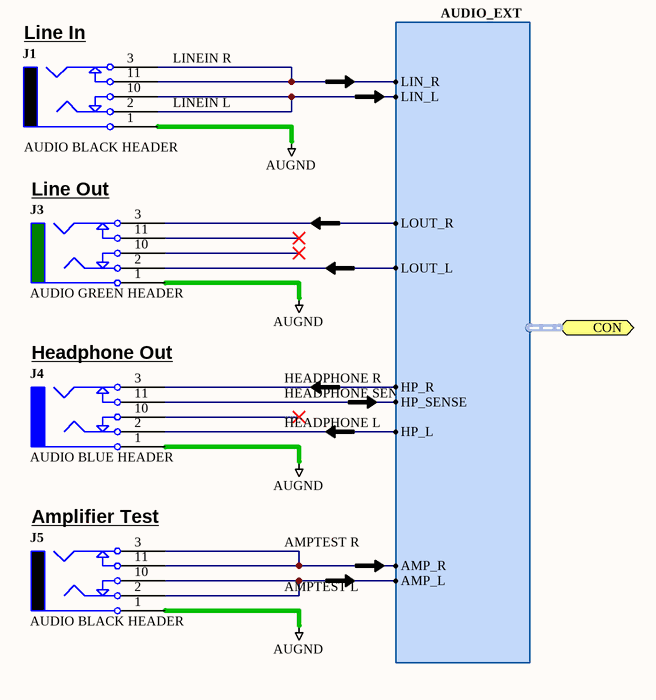
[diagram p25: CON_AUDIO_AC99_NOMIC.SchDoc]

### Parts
(Parts that share a designator on the sheet are numbered #1, #2 ... from top to bottom, then left to right.)
J1#4  AUDIO BLACK HEADER  [TSH-3675]
J3#2  AUDIO GREEN HEADER  [TSH-3675]
J4  AUDIO BLUE HEADER  [TSH-3675]
J5  AUDIO BLACK HEADER  [TSH-3675]

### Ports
CON (harness AUDIO_EXT)

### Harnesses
AUDIO_EXT: AMP_L, AMP_R, HP_L, HP_R, HP_SENSE, LIN_L, LIN_R, LOUT_L, LOUT_R

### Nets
AUGND: J1#4.1 J3#2.1 J4.1 J5.1
NetJ1#4_2: J1#4.2 J1#4.10 ; port CON.LIN_L
NetJ1#4_3: J1#4.3 J1#4.11 ; port CON.LIN_R
NetJ3#2_2: J3#2.2 ; port CON.LOUT_L
NetJ3#2_3: J3#2.3 ; port CON.LOUT_R
NetJ4_2: J4.2 ; port CON.HP_L
NetJ4_3: J4.3 ; port CON.HP_R
NetJ4_11: J4.11 ; port CON.HP_SENSE
NetJ5_2: J5.2 J5.10 ; port CON.AMP_L
NetJ5_3: J5.3 J5.11 ; port CON.AMP_R

Not connected (* = marked no-connect by the designer): J3#2 10* 11*; J4 10*

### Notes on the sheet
- (near J1#4) Line In
- LINEIN R
- LINEIN L
- (near J3#2) Line Out
- (near J4) Headphone Out
- HEADPHONE R
- HEADPHONE L
- HEADPHONE SENSE
- (near J5) Amplifier Test
- AMPTEST R
- AMPTEST L

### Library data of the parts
J1#4 J5 = D-300-0033: Connector, 3.5mm Stereo Audio Socket, Black, 2 break contacts (normals) and 2 auxiliary make contacts
J3#2 = D-300-0031: Connector, 3.5mm Stereo Audio Socket, Green, 2 break contacts (normals) and 2 auxiliary make contacts
J4 = D-300-0032: Connector, 3.5mm Stereo Audio Socket, Blue, 2 break contacts (normals) and 2 auxiliary make contacts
